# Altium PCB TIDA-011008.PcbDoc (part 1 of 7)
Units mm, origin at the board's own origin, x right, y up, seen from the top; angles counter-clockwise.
Board outline 252 x 205 mm, 4 copper layers (Top Layer, Inner Layer 1, Inner Layer 2, Bottom Layer), stack 1.926 mm thick; 517 components, 293 nets, 1426 pads, 1855 vias.
Unrouted connection lines stored in the file: 4.
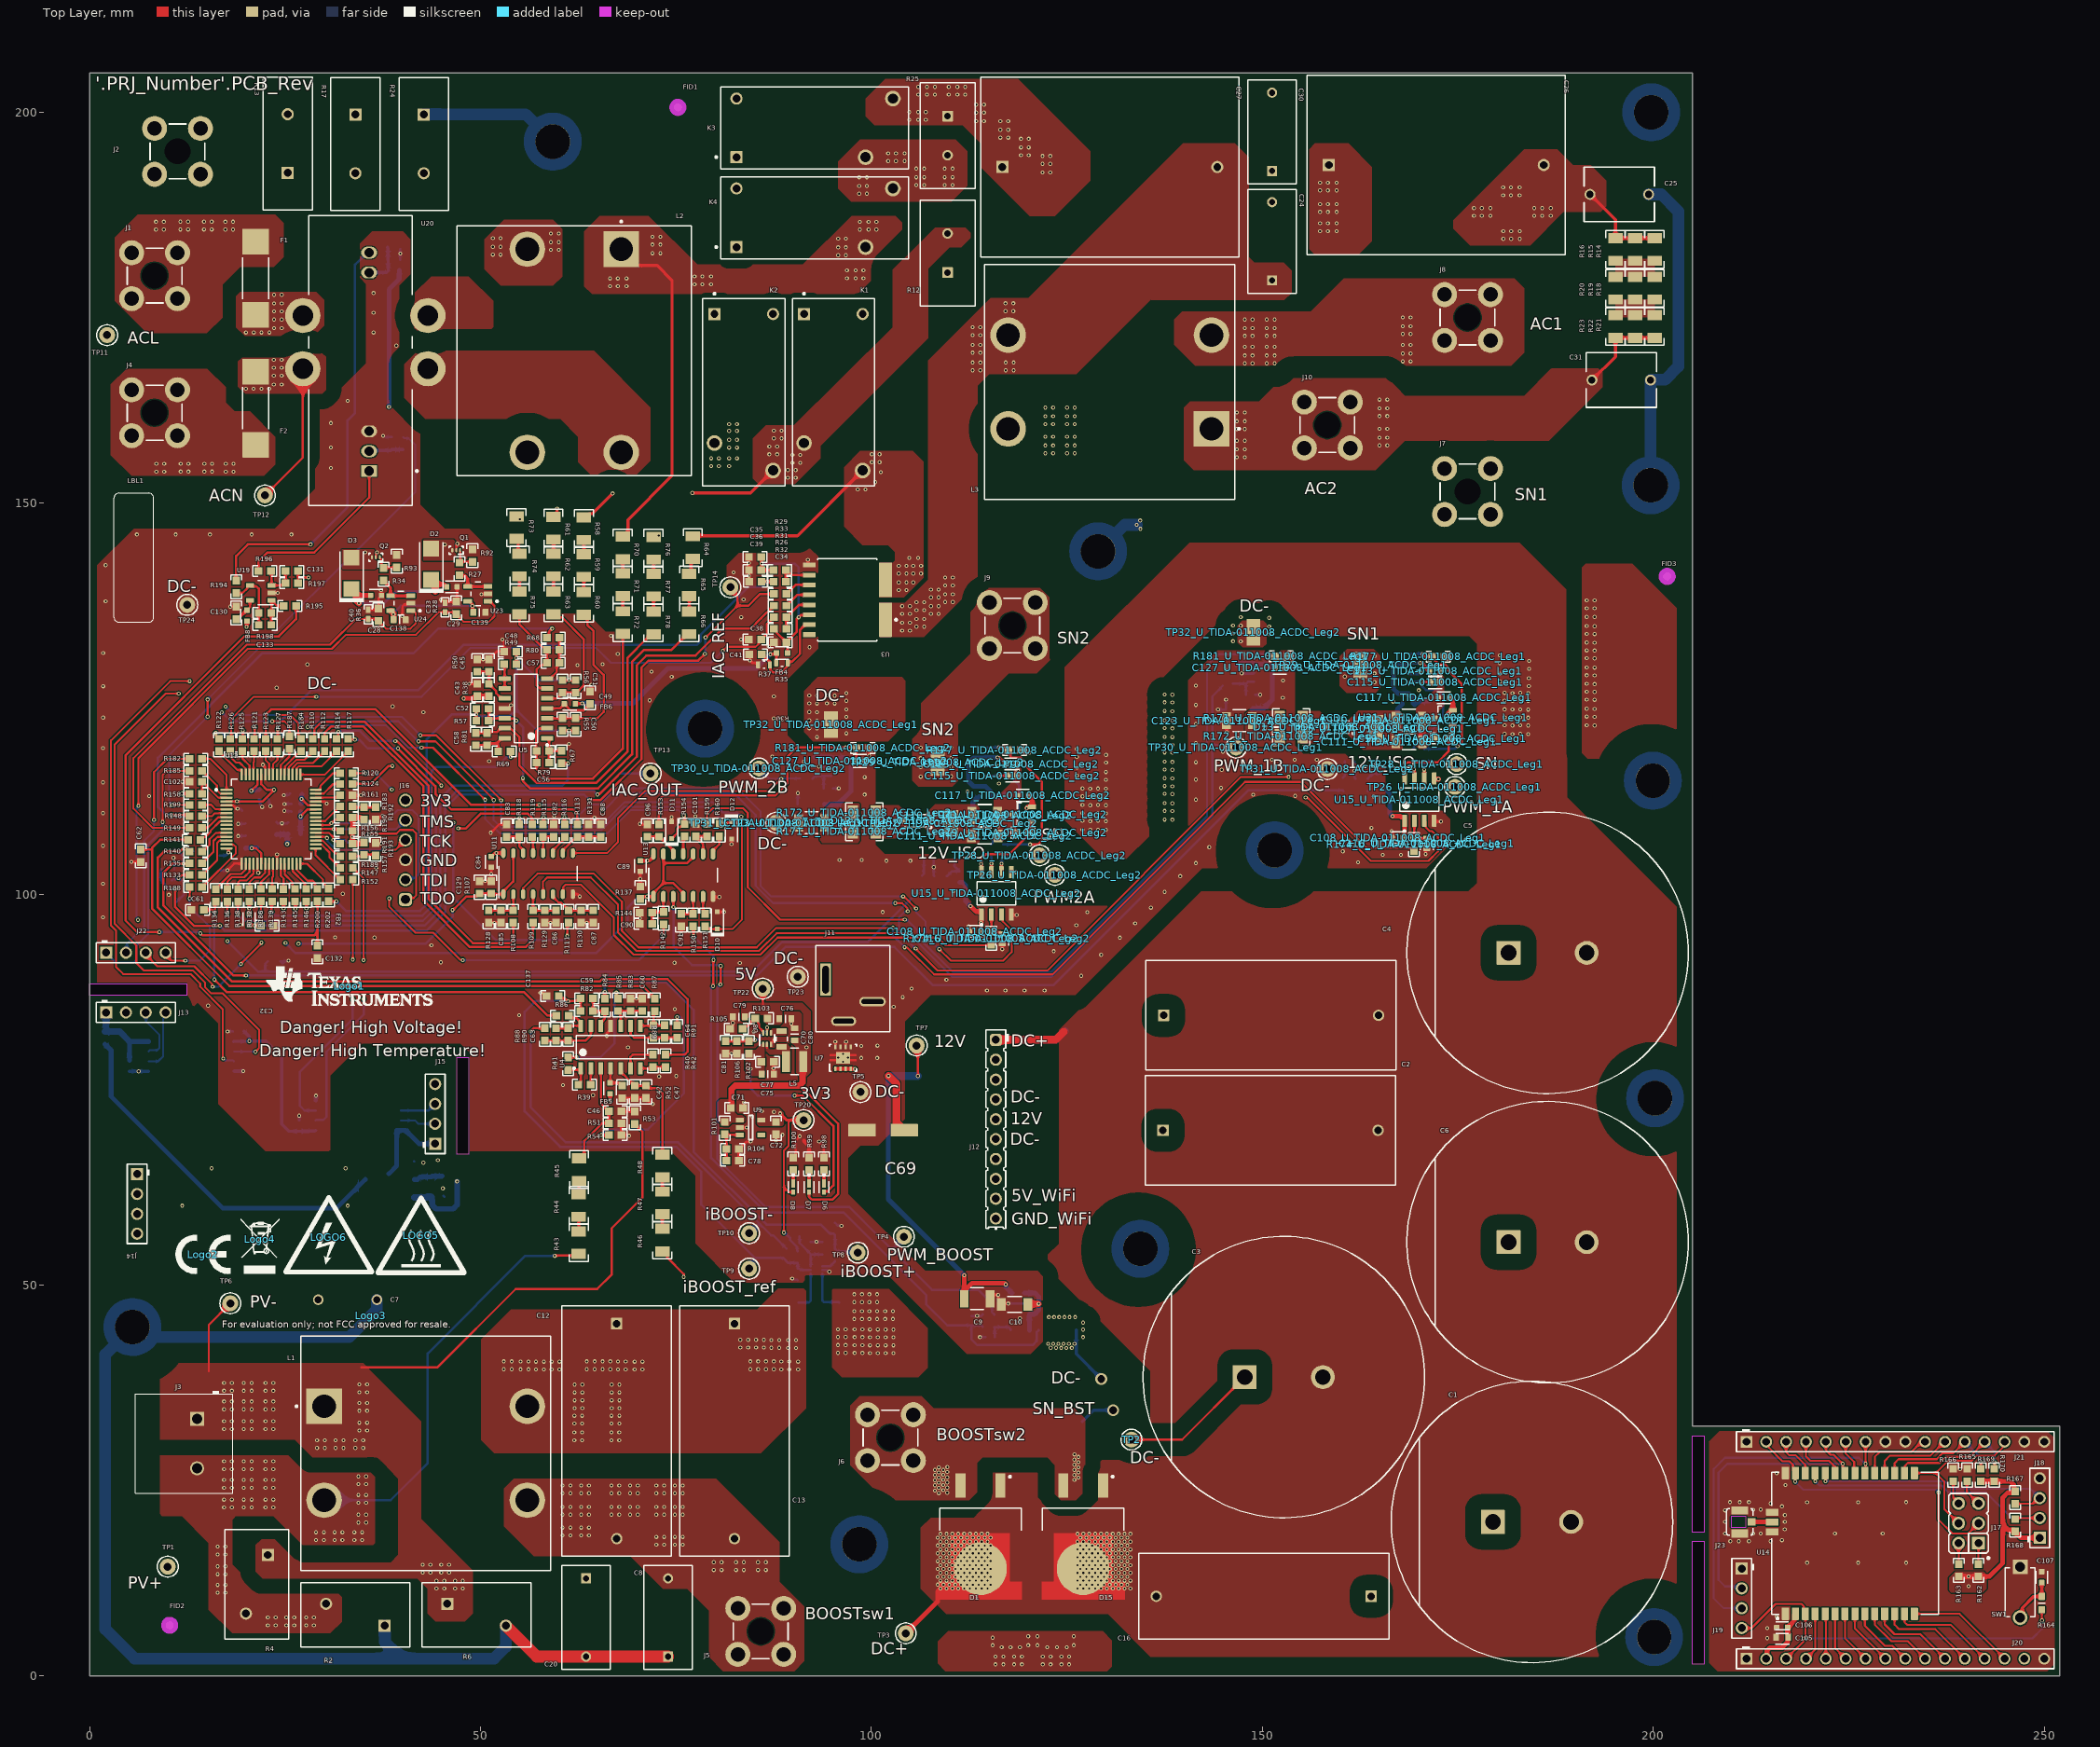
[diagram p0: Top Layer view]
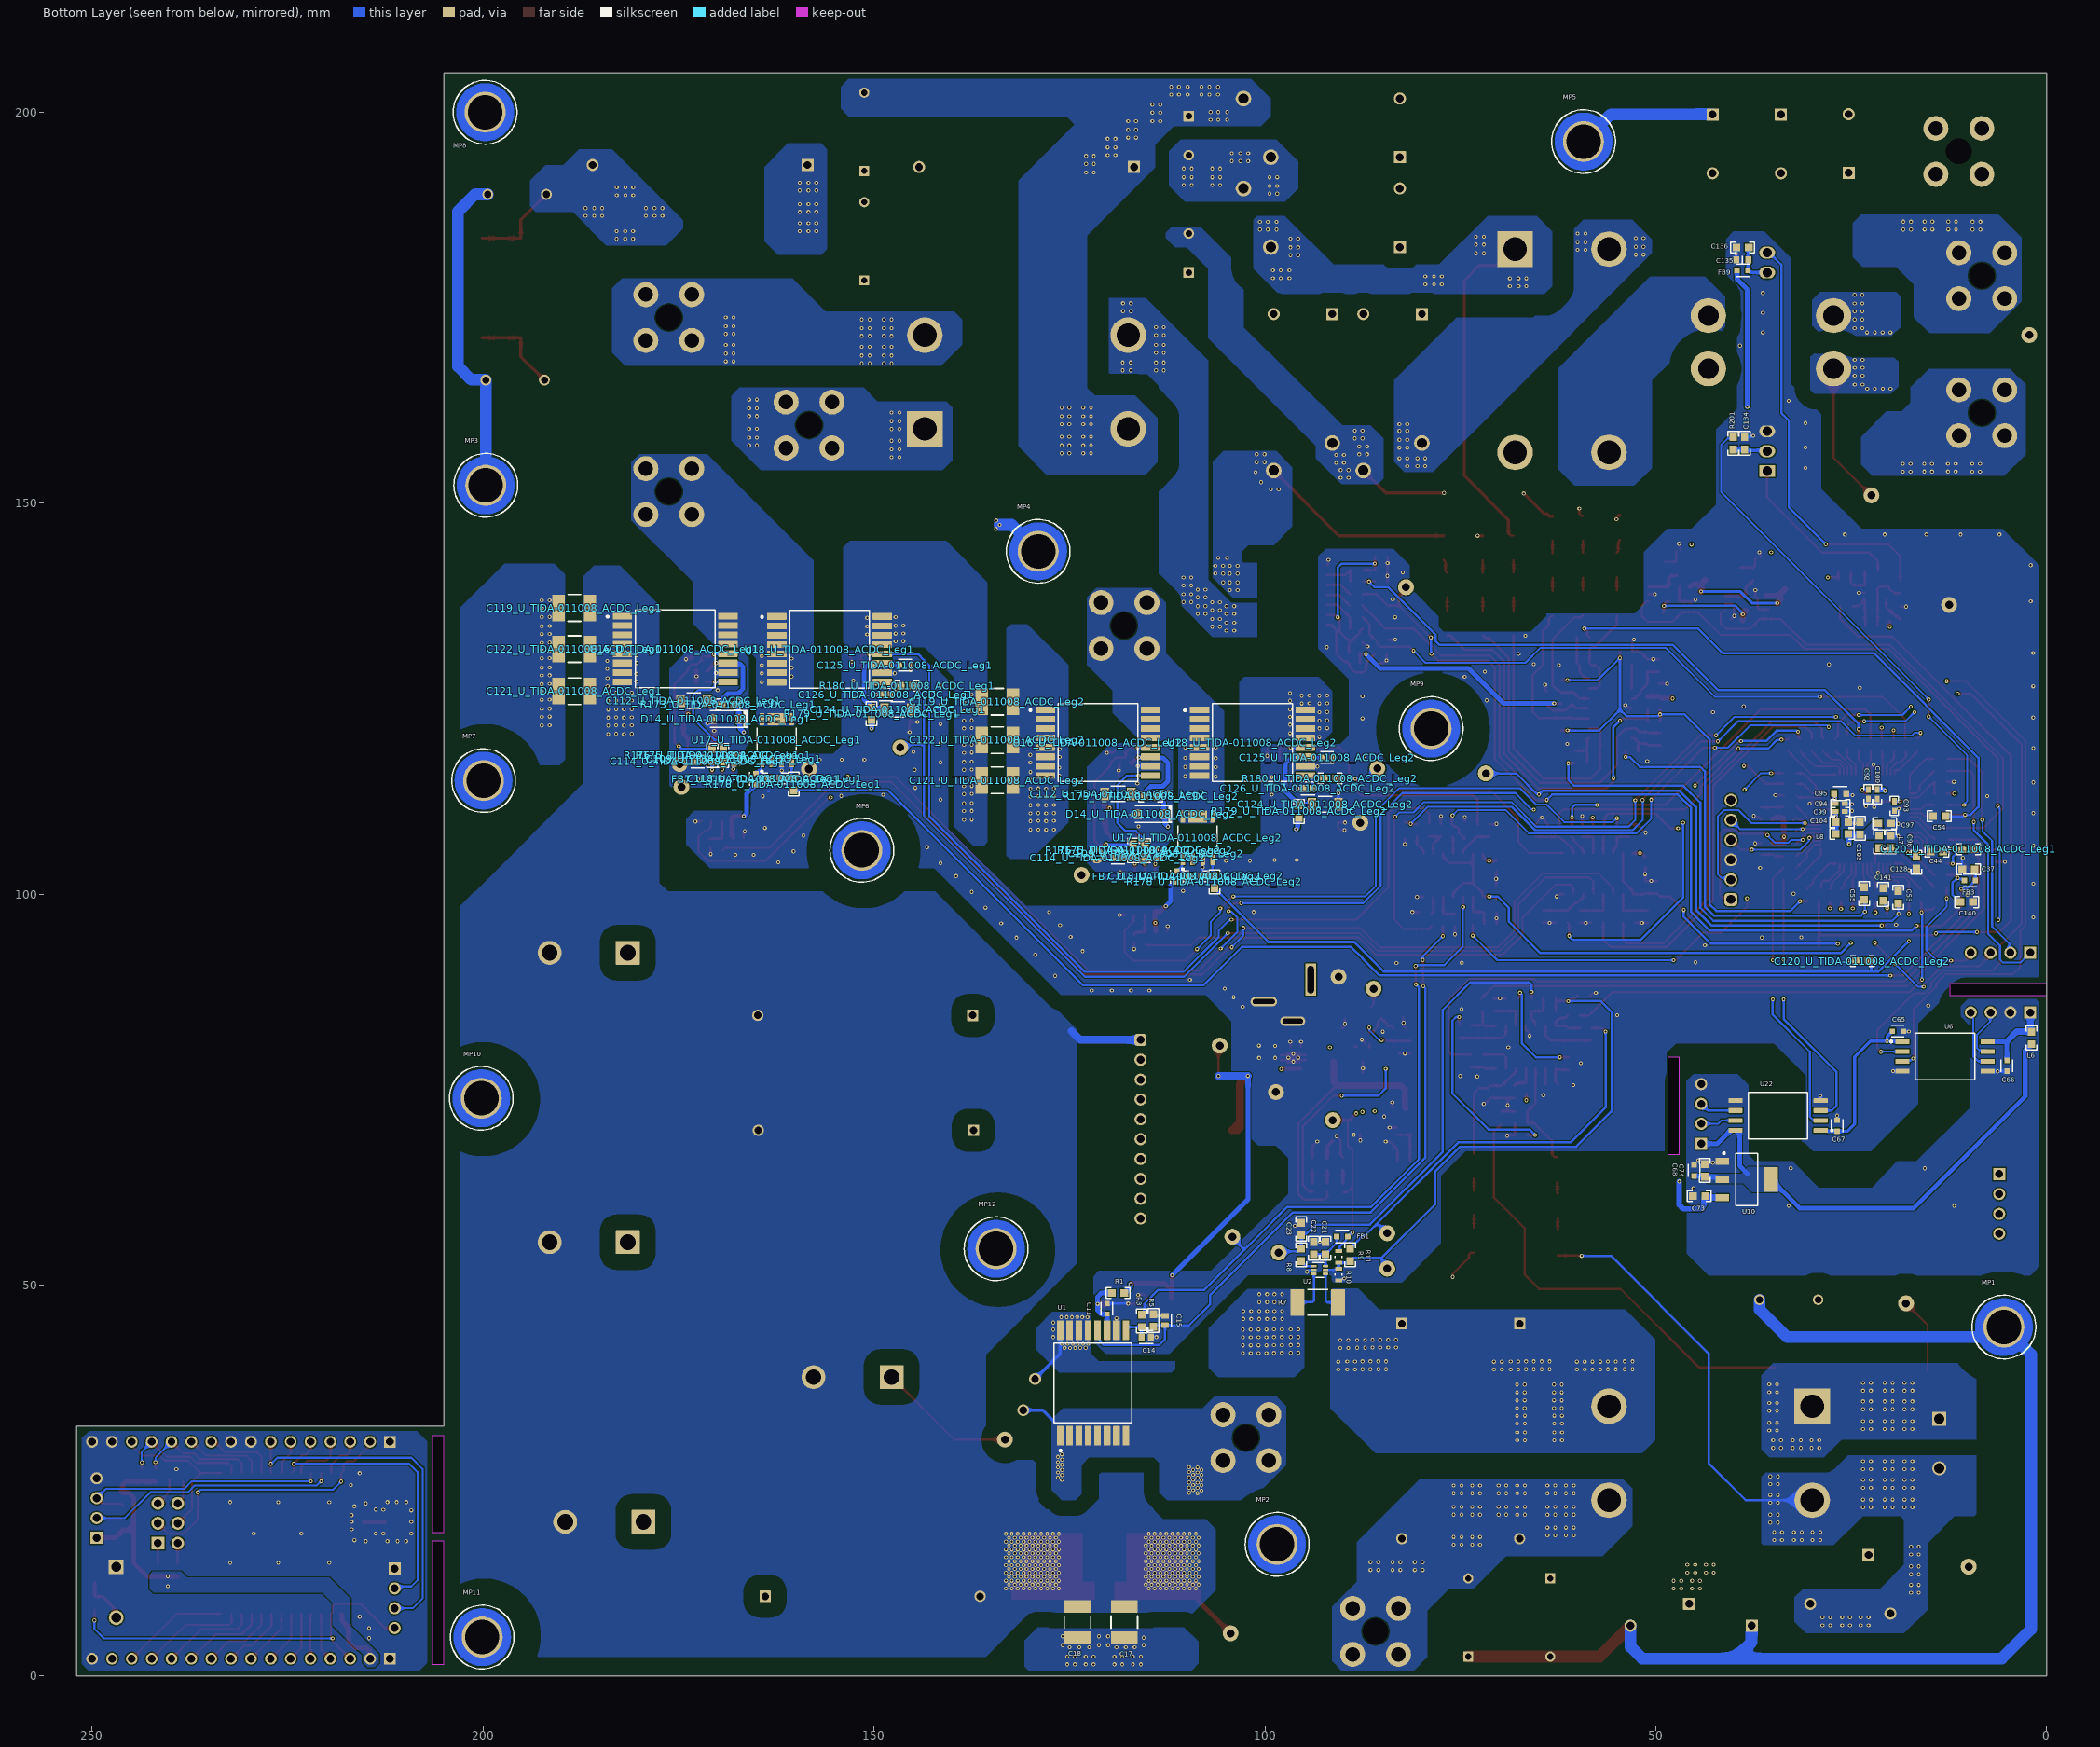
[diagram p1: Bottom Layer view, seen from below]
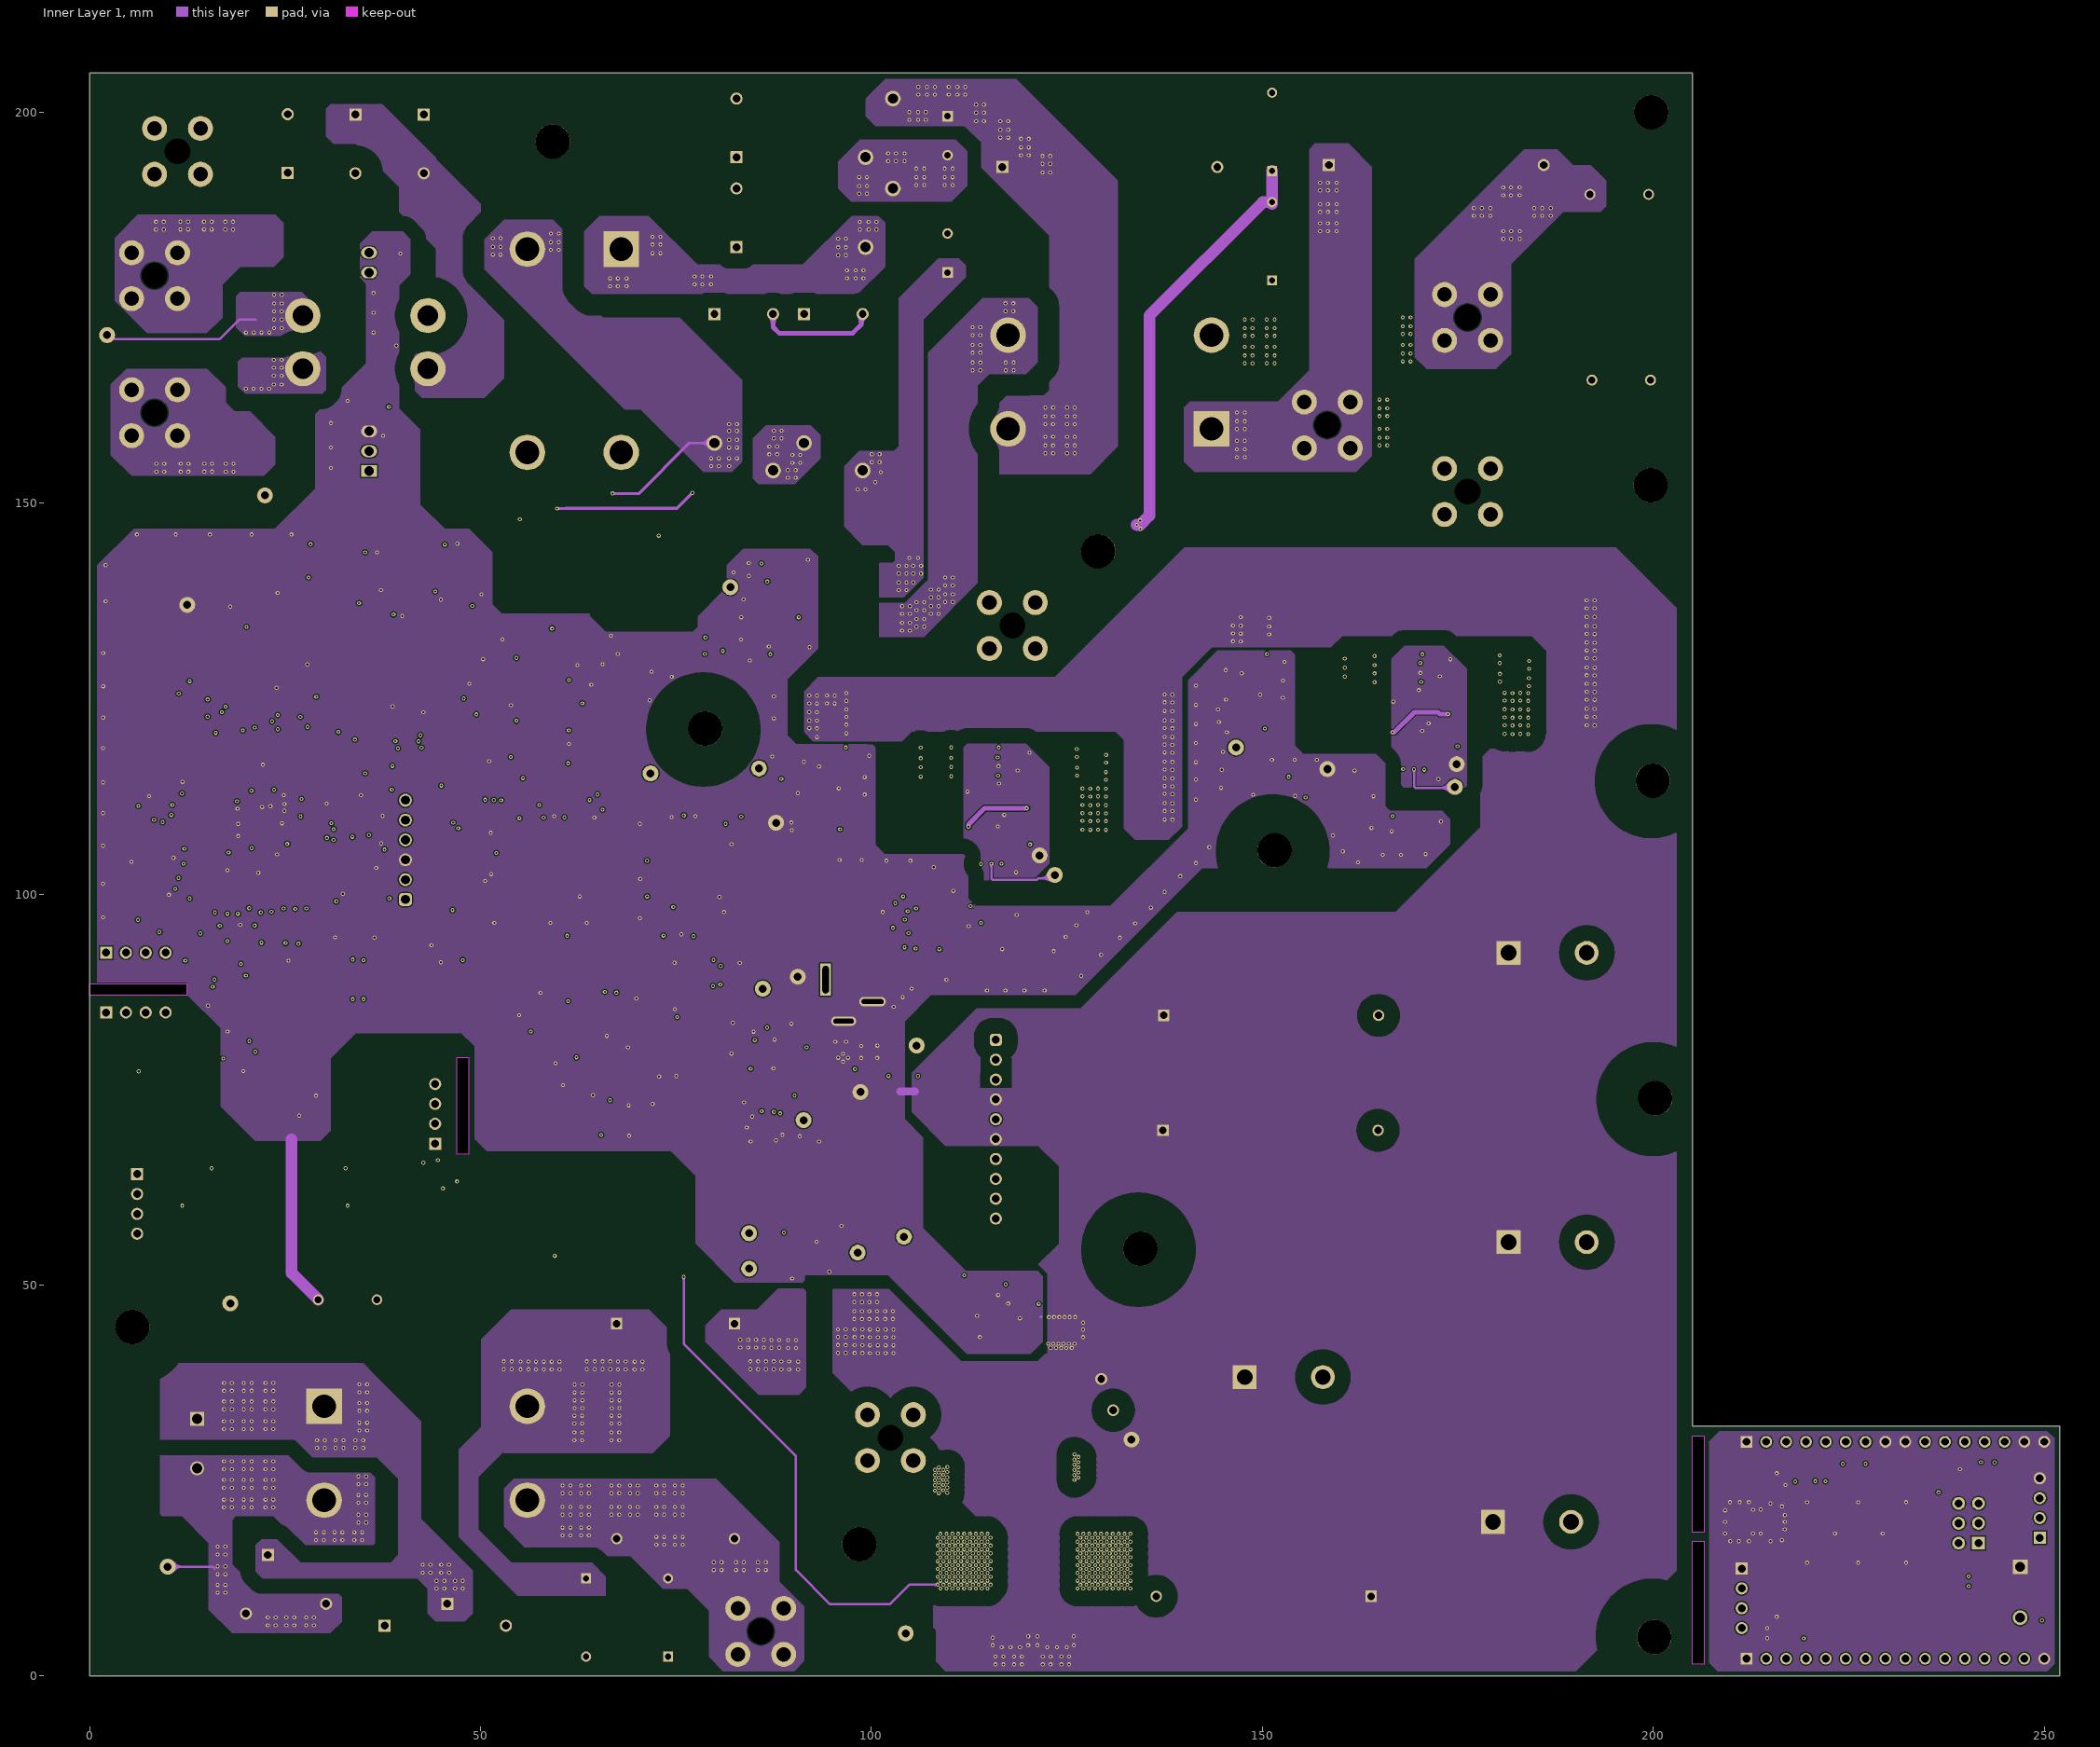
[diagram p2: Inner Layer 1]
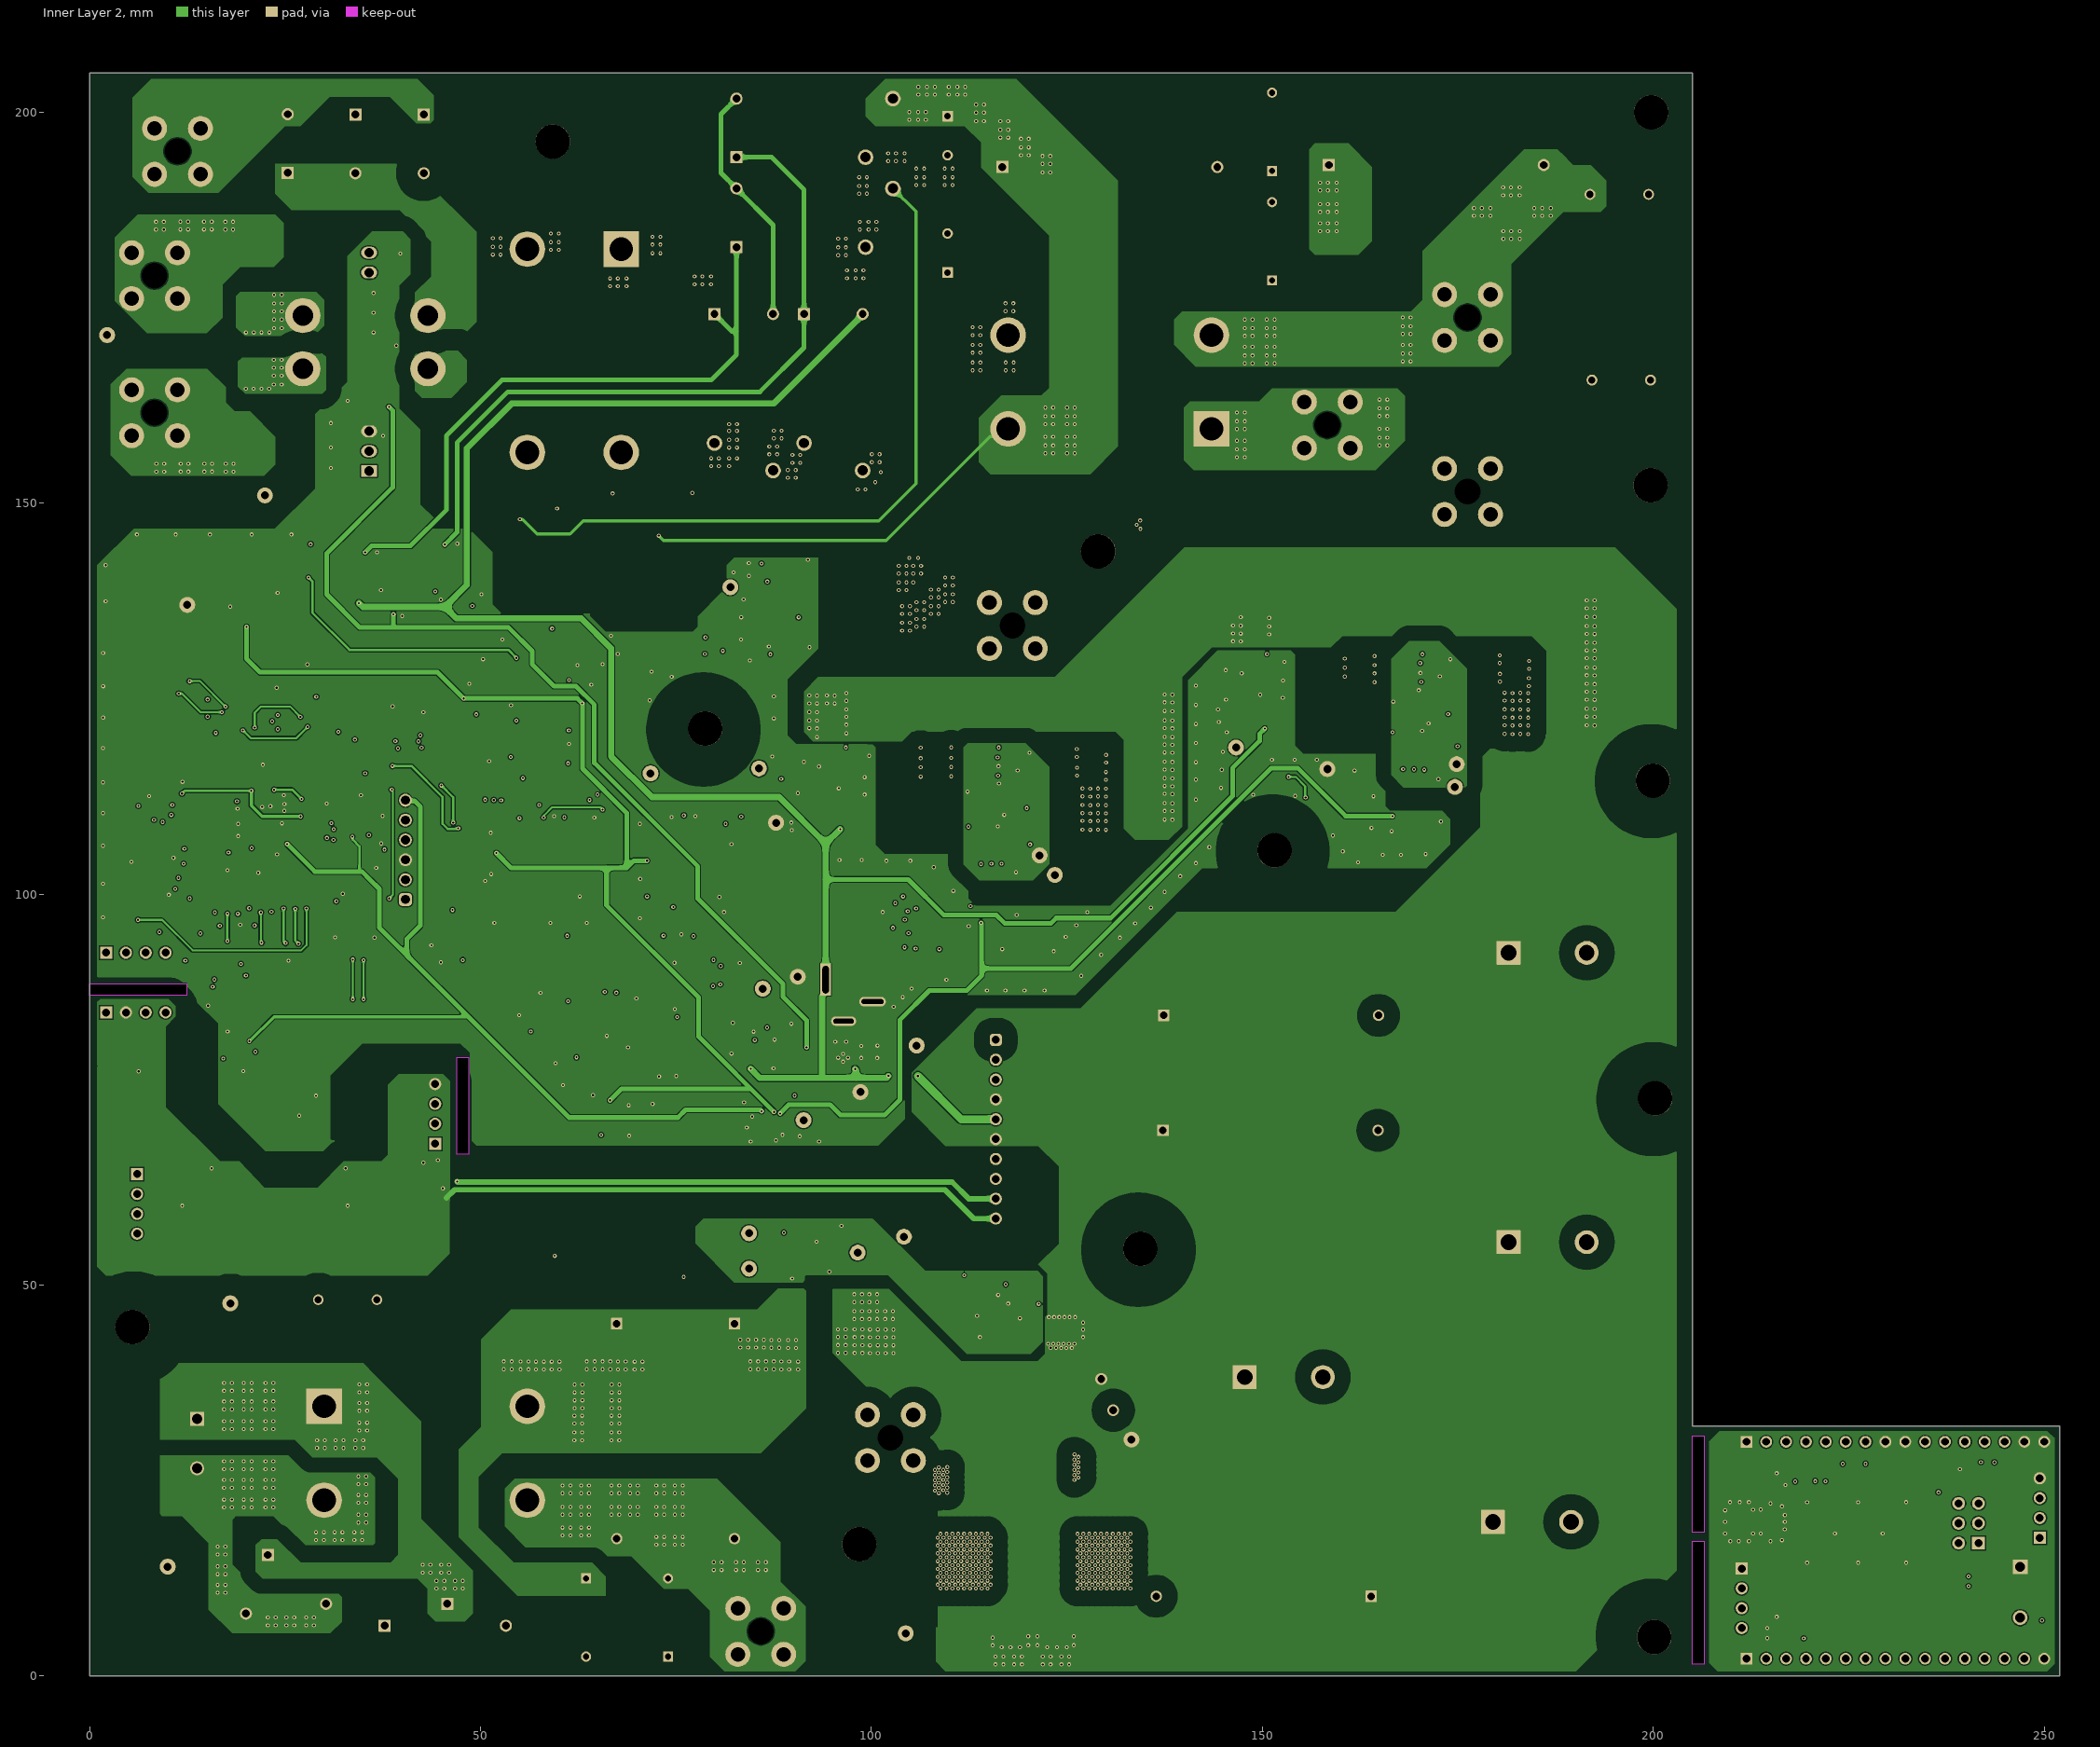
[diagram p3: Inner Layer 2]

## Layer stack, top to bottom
Top Solder: solder mask 0.0102, Solder Resist, Dk 3.5
Top Layer: signal copper 0.07
Dielectric 1: prepreg 0.0711, PP-006, Dk 4.1
Inner Layer 1: signal copper 0.07
Dielectric1: core 1.5037, FR-4 High Tg, Dk 4.8
Inner Layer 2: signal copper 0.07
Dielectric 2: prepreg 0.0711, PP-006, Dk 4.1
Bottom Layer: signal copper 0.07
Bottom Solder: solder mask 0.0102, Solder Resist, Dk 3.5

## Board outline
0,0 0,205 205,205 205,32 252,32 252,0
cut-out: 48.503,66.751 47.003,66.751 47.003,79.129 48.503,79.129
cut-out: 0.015,87.059 0.015,88.559 12.393,88.559 12.393,87.059
cut-out: 205,17.25 206.5,17.25 206.5,1.5 205,1.5
cut-out: 205,30.75 206.5,30.75 206.5,18.372 205,18.372

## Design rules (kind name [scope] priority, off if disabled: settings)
AcuteAngle [All] p1: minimum=4.50000000000000E+0001 checktracksonly=FALSE
AssemblyTestPointUsage [All] p1: valid=2
BoardOutlineClearance BoardOutlineClearance_MountingHoles [OnCopper and InComponentClass('Mounting Holes')] p1: gap=1 ignorepadtopadclearanceinfootprint=FALSE
BoardOutlineClearance BoardOutlineClearance_Poly [OnCopper and IsPoly] p2: gap=0.635 ignorepadtopadclearanceinfootprint=FALSE
BoardOutlineClearance [OnCopper and Not InComponentClass('Logo') and not InComponentClass('FiducialMark') and not InRegion(1000,500,4000,800) and not InPoly] p3: gap=1.016 ignorepadtopadclearanceinfootprint=FALSE
Clearance WiFi_HVN [InNetClass('GND_WiFi') vs InNetClass('HVN')] p1: gap=2.8 ignorepadtopadclearanceinfootprint=TRUE
Clearance SW_AC_Top [InNetClass('HV_SW1') vs (InNetClass('ACL')or InNetClass('ACN'))and (OnLayer('Top Layer') OR OnLayer('Bottom Layer'))] p2: gap=2 ignorepadtopadclearanceinfootprint=TRUE
Clearance SW_AC_Inner [InNetClass('HV_SW1') vs (InNetClass('ACL')or InNetClass('ACN'))and (OnLayer('Inner Layer 1') OR OnLayer('Inner Layer 2'))] p3: gap=1 ignorepadtopadclearanceinfootprint=TRUE
Clearance HVP_BOOST_SW_TOP [InNetClass('HVP') vs (InNetClass('HV_BOOST') or InNetClass('HV_BOOST_SW')) and (OnLayer('Top Layer') OR OnLayer('Bottom Layer'))] p4: gap=2 ignorepadtopadclearanceinfootprint=TRUE
Clearance HVP_BOOST_SW_INNER [InNetClass('HVP') vs (InNetClass('HV_BOOST') or InNetClass('HV_BOOST_SW')) and (OnLayer('Inner Layer 1') OR OnLayer('Inner Layer 2'))] p5: gap=1 ignorepadtopadclearanceinfootprint=TRUE
Clearance "Clearance Top HVN-HV" [InNetClass('HVN') vs (InNetClass('HVP') or InNetClass('HV_BOOST') or  InNetClass('HV_BOOST_SW') or InNetClass('HV_SW1') or InNetClass('ACN') or InNetClass('ACL'))] p6: gap=2 ignorepadtopadclearanceinfootprint=TRUE
Clearance "Clearance Inner HVN-HV" [InNetClass('HVN') vs (InNetClass('HVP') or InNetClass('HV_BOOST') or  InNetClass('HV_BOOST_SW') or InNetClass('HV_SW1') or InNetClass('ACN') or InNetClass('ACL')) and (OnLayer('Inner Layer 1') OR OnLayer('Inner Layer 2'))] p7: gap=1 ignorepadtopadclearanceinfootprint=TRUE
Clearance BUCK [InNetClass('HVP')   OR InNetClass('HVN') vs InNetClass('Buck')] p8: gap=1.8 ignorepadtopadclearanceinfootprint=FALSE
Clearance SW1 [(InNetClass('HVN')) OR (InNetClass('HVP')) vs InNetClass('HV_SW1')] p9: gap=0.6 ignorepadtopadclearanceinfootprint=FALSE
Clearance SW_BOOST [(InNetClass('HVP') or InNetClass('HV_BOOST') or  InNetClass('HV_BOOST_SW')) vs InNetClass('HV_SW1') or (InNetClass('ACN')) or (InNetClass('ACL'))] p10: gap=2.8 ignorepadtopadclearanceinfootprint=FALSE
Clearance ACL_ACN [InNetClass('ACL') vs InNetClass('ACN')] p11: gap=2.8 ignorepadtopadclearanceinfootprint=FALSE
Clearance PE [InNetClass('PE')] p12 off: gap=2.5 ignorepadtopadclearanceinfootprint=FALSE
Clearance Minimum_Distance [All] p13: gap=0.15 ignorepadtopadclearanceinfootprint=FALSE
Clearance Clearance_Keepouts [((IsTrack Or IsArc) And Not InPoly) And IsFree and IsKeepOut vs ((IsTrack Or IsArc) And Not InPoly) And IsFree and IsKeepOut] p14: gap=0 ignorepadtopadclearanceinfootprint=FALSE
Clearance Clearance_Poly [InPolygon] p15: gap=0.254 ignorepadtopadclearanceinfootprint=TRUE
Clearance Clearance_FiducialMark [IsKeepOut and InComponentClass('FiducialMark') vs IsPad and InComponentClass('FiducialMark')] p16: gap=0 ignorepadtopadclearanceinfootprint=TRUE
ComponentClearance ComponentClearance_MountingHoles_FiducialMarks [InComponentClass('Mounting Holes') vs InComponentClass('FiducialMark')] p1: gap=1.27 collisioncheckmode=3 verticalgap=0.254 showdistances=FALSE
ComponentClearance ComponentClearance_Shunt [InComponentClass('Header') vs InComponentClass('Shunt')] p2: gap=0 collisioncheckmode=3 verticalgap=0 showdistances=FALSE
ComponentClearance ComponentClearance_Logo [InComponentClass('Logo')] p3: gap=0 collisioncheckmode=3 verticalgap=0 showdistances=FALSE
ComponentClearance ComponentClearance_ScrewToNut [(HasFootprint('NY PMS 440 0025 PH')) vs (HasFootprint('Keystone_1902C'))] p4: gap=0.127 collisioncheckmode=3 verticalgap=0.254 showdistances=FALSE
ComponentClearance ComponentClearance_MountingHoles [InComponentClass('Mounting Holes')] p5: gap=2.54 collisioncheckmode=3 verticalgap=2540 showdistances=FALSE
ComponentClearance ComponentClearance_SmallPassives [HasFootprint('0201*') or HasFootprint('0402*') or HasFootprint('0508') or HasFootprint('0603*') or HasFootprint('0612') or HasFootprint('0805*') or HasFootprint('0815*') or HasFootprint('0830*') or HasFootprint('1206*') or HasFootprint('1210*') or HasFootprint('1808*') or HasFootprint('1812*') or HasFootprint('1825*') or HasFootprint('2010*') or HasFootprint('2220*') or HasFootprint('2225*') or HasFootprint('2512*') or HasFootprint('2728*') or HasFootprint('3518*') vs HasFootprint('0201*') or HasFootprint('0402*') or HasFootprint('0508') or HasFootprint('0603*') or HasFootprint('0612') or HasFootprint('0805*') or HasFootprint('0815*') or HasFootprint('0830*') or HasFootprint('1206*') or HasFootprint('1210*') or HasFootprint('1808*') or HasFootprint('1812*') or HasFootprint('1825*') or HasFootprint('2010*') or HasFootprint('2220*') or HasFootprint('2225*') or HasFootprint('2512*') or HasFootprint('2728*') or HasFootprint('3518*')] p6: gap=0.38 collisioncheckmode=3 verticalgap=0.254 showdistances=FALSE
ComponentClearance ComponentClearance_THtoSMT [IsThruComponent vs IsSMTComponent] p7: gap=0.01 collisioncheckmode=3 verticalgap=0.01 showdistances=FALSE
ComponentClearance ComponentClearance_THtoTH [IsThruComponent vs IsThruComponent] p8: gap=0.1 collisioncheckmode=3 verticalgap=0.1 showdistances=FALSE
ComponentClearance [All] p9: gap=0.01 collisioncheckmode=3 verticalgap=0.01 showdistances=FALSE
DiffPairsRouting [All] p1: maxlimit=2.54 minlimit=0.254 mostfreqgap=0.254 toplayer_minwidth=0.381 toplayer_maxwidth=0.381 toplayer_prefwidth=0.381 midlayer1_minwidth=0.381 midlayer1_maxwidth=0.381 midlayer1_prefwidth=0.381 midlayer2_minwidth=0.381 midlayer2_maxwidth=0.381 midlayer2_prefwidth=0.381 bottomlayer_minwidth=0.381 bottomlayer_maxwidth=0.381 bottomlayer_prefwidth=0.381 maxuncoupledlength=25.4
FabricationTestPointUsage TestPointUsage [All] p1: valid=2 allowmultiple=FALSE
FabricationTestpoint Testpoint [All] p1: side=3 testpointundercomponent=TRUE minsize=1.016 maxsize=2.54 preferedsize=1.524 minholesize=0 maxholesize=1.016 preferedholesize=0.813 testpointgrid=0.025 allowsidetop=TRUE allowsidebottom=TRUE usegrid=TRUE gridtolerance=0
FanoutControl Fanout_LCC [IsLCC] p1: bgadir=Out bgaviamode=Centered fanoutstyle=Auto fanoutdirection=Alternating viagrid=0.025 // Fanout_LCC (Default Rule)
FanoutControl Fanout_BGA [IsBGA] p2: bgadir=Out bgaviamode=Centered fanoutstyle=Auto fanoutdirection=Alternating viagrid=0.025 // Fanout_BGA (Default Rule)
FanoutControl Fanout_Default [All] p4: bgadir=Out bgaviamode=Centered fanoutstyle=Auto fanoutdirection=Alternating viagrid=0.025 // Fanout_Default (Default Rule)
FanoutControl Fanout_Small [(CompPinCount < 5)] p5: bgadir=Out bgaviamode=Centered fanoutstyle=Auto fanoutdirection=OutThenIn viagrid=0.025 // Fanout_Small (Default Rule)
HoleSize [All] p1: absolutevalues=TRUE maxlimit=6.375 minlimit=0.2 maxpercent=80.000 minpercent=20.000
MinimumAnnularRing MinimumAnnularRing_ThermalPadVias [IsVia and InAnyComponent] p1: minimumring=0.15
MinimumAnnularRing [All] p2: minimumring=0.125
MinimumSolderMaskSliver MinimumSolderMaskSliver_Logo [InComponentClass('Logo') vs InComponentClass('Logo')] p1: minsoldermaskwidth=0.018
MinimumSolderMaskSliver [All] p2: minsoldermaskwidth=0
PlaneConnect [All] p1: planeconnectstyle=Relief reliefexpansion=0.254 reliefentries=4 reliefconductorwidth=0.254 reliefairgap=0.254
PolygonConnect PolygonConnect_1 [All] p1: connectstyle=Direct reliefconductorwidth=1 reliefentries=4 polygonreliefangle="90 Angle" airgapwidth=0.254
PolygonConnect "GaN 2" [IsNamedPolygon('BOTTOM_LAYER_SN2_P047') vs HasFootprint('KLF0016A-MFG')] p2: connectstyle=Relief reliefconductorwidth=0.254 reliefentries=4 polygonreliefangle="90 Angle" airgapwidth=0.254
PolygonConnect "GaN 3" [IsNamedPolygon('BOTTOM_LAYER_SW_MID_P059')] p3: thpad.connectstyle=Direct thpad.reliefconductorwidth=0.254 thpad.reliefentries=4 thpad.polygonreliefangle="90 Angle" thpad.airgapwidth=0.254 smdpad.connectstyle=Relief smdpad.reliefconductorwidth=0.254 smdpad.reliefentries=4 smdpad.polygonreliefangle="90 Angle" smdpad.airgapwidth=0.254 via.connectstyle=Direct via.reliefconductorwidth=0.254 via.reliefentries=4 via.polygonreliefangle="90 Angle" via.airgapwidth=0.254
PolygonConnect "GaN 4" [IsNamedPolygon('BOTTOM_LAYER_DC_BUS+_P066')] p4: thpad.connectstyle=Direct thpad.reliefconductorwidth=0.254 thpad.reliefentries=4 thpad.polygonreliefangle="90 Angle" thpad.airgapwidth=0.254 smdpad.connectstyle=Relief smdpad.reliefconductorwidth=0.254 smdpad.reliefentries=4 smdpad.polygonreliefangle="90 Angle" smdpad.airgapwidth=0.254 via.connectstyle=Direct via.reliefconductorwidth=0.254 via.reliefentries=4 via.polygonreliefangle="90 Angle" via.airgapwidth=0.254
PolygonConnect "GaN 5" [IsNamedPolygon('Bottom Layer-SW_1')] p5: thpad.connectstyle=Direct thpad.reliefconductorwidth=0.254 thpad.reliefentries=4 thpad.polygonreliefangle="90 Angle" thpad.airgapwidth=0.254 smdpad.connectstyle=Relief smdpad.reliefconductorwidth=0.254 smdpad.reliefentries=4 smdpad.polygonreliefangle="90 Angle" smdpad.airgapwidth=0.254 via.connectstyle=Direct via.reliefconductorwidth=0.254 via.reliefentries=4 via.polygonreliefangle="90 Angle" via.airgapwidth=0.254
PolygonConnect "GaN 6" [IsNamedPolygon('BOTTOM_LAYER_DC_BUS+_P007')] p6: thpad.connectstyle=Direct thpad.reliefconductorwidth=0.254 thpad.reliefentries=4 thpad.polygonreliefangle="90 Angle" thpad.airgapwidth=0.254 smdpad.connectstyle=Relief smdpad.reliefconductorwidth=0.254 smdpad.reliefentries=4 smdpad.polygonreliefangle="90 Angle" smdpad.airgapwidth=0.254 via.connectstyle=Direct via.reliefconductorwidth=0.254 via.reliefentries=4 via.polygonreliefangle="90 Angle" via.airgapwidth=0.254
PolygonConnect "GaN 7" [IsNamedPolygon('BOTTOM_LAYER_DC_BUS-_P082')] p7: thpad.connectstyle=Direct thpad.reliefconductorwidth=0.254 thpad.reliefentries=4 thpad.polygonreliefangle="90 Angle" thpad.airgapwidth=0.254 smdpad.connectstyle=Relief smdpad.reliefconductorwidth=0.254 smdpad.reliefentries=4 smdpad.polygonreliefangle="90 Angle" smdpad.airgapwidth=0.254 via.connectstyle=Direct via.reliefconductorwidth=0.254 via.reliefentries=4 via.polygonreliefangle="90 Angle" via.airgapwidth=0.254
PolygonConnect [All] p8: connectstyle=Direct reliefconductorwidth=0.254 reliefentries=4 polygonreliefangle="90 Angle" airgapwidth=0.254
RoutingVias ThermalPadVias [IsVia and InAnyComponent] p1: holewidth=0.254 width=0.508 viastyle="Through Hole" minholewidth=0.2 minwidth=0.5 maxholewidth=1.016 maxwidth=1.651
RoutingVias [All] p2: holewidth=0.406 width=0.864 viastyle="Through Hole" minholewidth=0.2 minwidth=0.5 maxholewidth=1.016 maxwidth=1.651
SilkToBoardRegionClearance [Not ((IsComment or IsDesignator) And (Hide <> 'False')) and not InRegion(1000,500,4000,800)] p1:
SilkToSilkClearance SilkToSilkClearance_Pb-FreeLogo [(HasFootprint('Pb-Free_Overlay_Medium') OR HasFootprint('Pb-Free_Overlay_Small')) vs (HasFootprint('Pb-Free_Overlay_Medium') OR HasFootprint('Pb-Free_Overlay_Small'))] p1: silktosilkclearance=0
SilkToSilkClearance [All] p2: silktosilkclearance=0
SilkToSolderMaskClearance SilkToComponentPadClearance [(IsPad or IsFill or IsRegion) and InAnycomponent] p1: minsilkscreentomaskgap=0 clearancetoexposedcopper=TRUE
SilkToSolderMaskClearance "Silk to Solder Mask Opening" [All] p2: minsilkscreentomaskgap=0.01 clearancetoexposedcopper=FALSE
SolderMaskExpansion [All] p1: expansion=0.05 istentingtop=FALSE
UnRoutedNet [All] p1: checkbadconnections=TRUE
Width [All] p1: maxlimit=2.54 minlimit=0.25 preferedwidth=0.5 checkconnectedcopper=TRUE
14 further rules are at their usual default settings.

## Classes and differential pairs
net class GND_WiFi: ANT2 GND_WiFi GPRS_RX GPRS_TX LOGGER NetC66_2 NetC107_2 NetJ17_1 NetJ17_2 NetJ17_5 NetJ17_6 P12_GPIO32 P13_GPIO31 P14_GPIO30 P16_GPIO29 P17_GPIO28 P18_GPIO27 P19_GPIO26 P29_GPIO17 P30_GPIO16 P31_GPIO15 P32_GPIO14 P33_GPIO13 P34_GPIO12 P35_GPIO11 P36_GPIO10 P43_GPIO4 P44_GPIO3 P52_GPIO37 P53_GPIO36 RESET SWCLK SWDIO UART1_RX UART1_TX VCC_3V3_Wifi VCC_5V_WiFi
component class U_TIDA-011008_Hardware: !PCB FID1 FID2 FID3 LBL1 Logo1 Logo2 Logo3 Logo4 LOGO5 LOGO6 MP1 MP2 MP3 MP4 MP5 MP6 MP7 MP8 MP9 MP10 MP11 MP12
component class Logo: Logo1
component class Label: LBL1
component class FiducialMark: FID1 FID2 FID3
net class HV_BOOST_SW: NetD1_3
channel class TIDA-011008_ACDC_Leg: U_TIDA-011008_ACDC_Leg1 U_TIDA-011008_ACDC_Leg2
net class PE: PE PE1 PE2 PE3 PE4 PE5
net class HVP: DC_Bus+
net class HVN: CS_Boost CS_Boost+ CS_Boost- CS_Boost_ref DAC_A DC_Bus- Enable_DCAC Enable_DCDC FLT_1A FLT_1A_mcu FLT_1B FLT_1B_mcu FLT_2A FLT_2A_mcu FLT_2B FLT_2B_mcu FLT_Boost FLT_Boost_mcu GPIO24 GPIO28 GPIO29 GPIO32 GPIO227 IAC_F\A\U\L\T\ IAC_O\C\ IAC_OUT IAC_REF MCU_TCK MCU_TDI MCU_TDO MCU_TMS NetC10_1 NetC12_1 NetC21_1 NetC32_2 NetC34_1 NetC37_2 NetC41_1 NetC45_2 NetC49_1 NetC50_1 NetC51_1 NetC52_1 NetC56_1 NetC56_2 NetC57_1 NetC57_2 NetC58_1 NetC58_2 NetC59_2 NetC60_2 NetC63_1 NetC63_2 NetC64_1 NetC64_2 NetC70_1 NetC70_2 NetC78_2 NetC81_2 NetC82_1 NetC83_1 NetC85_1 NetC86_1 NetC87_1 NetC88_1 NetC90_1 NetC91_1 NetC96_1 NetC101_1 NetC102_1 NetC116_U_TIDA-011008_ACDC_Leg1_1 NetC116_U_TIDA-011008_ACDC_Leg2_1 NetC118_U_TIDA-011008_ACDC_Leg1_1 NetC118_U_TIDA-011008_ACDC_Leg2_1 NetC124_U_TIDA-011008_ACDC_Leg1_1 NetC124_U_TIDA-011008_ACDC_Leg2_1 NetC128_2 NetC130_1 NetC131_1 NetC133_1 NetC133_2 NetC134_1 NetD6_1 NetD7_1 NetD8_1 NetD13_U_TIDA-011008_ACDC_Leg1_2 NetD13_U_TIDA-011008_ACDC_Leg2_2 NetQ1_1 NetQ2_1 NetR8_1 NetR26_1 NetR27_1 NetR29_1 NetR30_1 NetR31_2 NetR34_1 NetR49_1 NetR103_1 NetR110_1 NetR112_1 NetR114_1 NetR116_1 NetR117_1 NetR119_1 NetR120_1 NetR121_1 NetR122_1 NetR123_1 NetR124_1 NetR125_1 NetR126_1 NetR127_1 NetR132_1 NetR133_1 NetR134_1 NetR135_1 NetR136_1 NetR138_1 NetR139_1 NetR140_1 NetR141_1 NetR143_1 NetR145_1 NetR146_1 NetR147_1 NetR148_1 NetR149_1 NetR151_1 NetR152_1 NetR154_1 NetR160_1 NetR161_1 NetR178_U_TIDA-011008_ACDC_Leg1_2 NetR178_U_TIDA-011008_ACDC_Leg2_2 NetR182_1 NetR183_1 NetR184_1 NetR185_1 NetR186_1 NetR187_1 NetR188_1 NetR189_1 NetR199_1 NetR200_1 NetR202_1 PV_Input- PV_Input_buffer+ PV_Input_buffer- PWM_1A PWM_1A_mcu PWM_1B PWM_1B_mcu PWM_2A PWM_2A_mcu PWM_2B PWM_2B_mcu PWM_Boost PWM_Boost_mcu PWMiN_B_U_TIDA-011008_ACDC_Leg1 PWMiN_B_U_TIDA-011008_ACDC_Leg2 PWMiN_Boost Relay_Precharge Relay_Precharge_mcu Relay_Safe Relay_Safe_mcu SCIA_RX SCIA_TX SCIB_RX SCIB_TX TEMP_SW1 TEMP_SW2 V_ZCD VAC_input VAC_relay VAC_sw VCC_1V2 VCC_1V65 VCC_3V3 VCC_5V VCC_12V VCC_ZCD VCCA_3V3 VCCIO_3V3 VDC_sense Vout_ZCD VPV_sense Vref_ZCD ZCD_CHK
net class HV_SW1: FLT_A_LMG_U_TIDA-011008_ACDC_Leg1 FLT_A_LMG_U_TIDA-011008_ACDC_Leg2 LDO5V_SN_U_TIDA-011008_ACDC_Leg1 LDO5V_SN_U_TIDA-011008_ACDC_Leg2 NetC112_U_TIDA-011008_ACDC_Leg1_1 NetC112_U_TIDA-011008_ACDC_Leg2_1 NetC114_U_TIDA-011008_ACDC_Leg1_2 NetC114_U_TIDA-011008_ACDC_Leg2_2 NetR175_U_TIDA-011008_ACDC_Leg1_1 NetR175_U_TIDA-011008_ACDC_Leg2_1 PWMiN_A_U_TIDA-011008_ACDC_Leg1 PWMiN_A_U_TIDA-011008_ACDC_Leg2 SN1 SN2 SN_U_TIDA-011008_ACDC_Leg1 SN_U_TIDA-011008_ACDC_Leg2 VCC_12V_SN_U_TIDA-011008_ACDC_Leg1 VCC_12V_SN_U_TIDA-011008_ACDC_Leg2
net class HV_BOOST: NetC8_2 PV_Input+
net class ACN: AC_N NetC26_1 NetF2_1 NetL2_4 VAC_N VAC_N_Relay VAC_N_SW
net class ACL: AC_L NetC24_1 NetC25_2 NetF1_1 NetL2_3 VAC_L VAC_L_Relay VAC_L_SW
component class "U_TIDA-011008_WiFi Module": ANT1 C105 C106 C107 J17 J18 J19 J20 J21 J23 R162 R163 R164 R165 R166 R167 R168 R169 R170 SW1 U14
component class "U_TIDA-011008_Measurements & AD Buffer": C42 C43 C44 C45 C46 C47 C48 C49 C50 C51 C52 C53 C54 C55 C56 C57 C58 C59 C60 C61 C62 C63 C64 C130 C131 C132 C133 FB5 FB6 FB8 R38 R39 R40 R41 R42 R43 R44 R45 R46 R47 R48 R49 R50 R51 R52 R53 R54 R55 R56 R57 R58 R59 R60 R61 R62 R63 R64 R65 R66 R67 R68 R69 R70 R71 R72 R73 R74 R75 R76 R77 R78 R79 R80 R81 R82 R83 R84 R85 R86 R87 R88 R89 R90 R91 R194 R195 R196 R197 R198 U4 U5 U19
component class "U_TIDA-011008_Control Stage": C65 C66 C67 C68 C73 C74 C82 C83 C84 C85 C86 C87 C88 C89 C90 C91 C92 C93 C94 C95 C96 C97 C98 C99 C100 C101 C102 C103 C104 C128 C129 D10 D11 D12 J13 J14 J15 J16 J22 L6 L7 L8 R107 R109 R110 R112 R113 R114 R115 R116 R117 R118 R119 R120 R121 R122 R123 R124 R125 R126 R127 R128 R129 R130 R131 R132 R133 R134 R135 R136 R137 R138 R139 R140 R141 R142 R143 R144 R145 R146 R147 R148 R149 R150 R151 R152 R153 R154 R155 R156 R157 R158 R159 R160 R161 R182 R183 R184 R185 R186 R187 R188 R189 R190 R191 R192 R193 R199 R200 R202 TP24 U6 U10 U11 U12 U13 U22
component class U_TIDA-011008_Boost: C8 C9 C10 C11 C12 C13 C14 C15 C16 C17 C18 C20 C21 C22 C23 C137 D1 D15 FB1 J5 J6 L1 R1 R2 R3 R4 R5 R6 R7 R8 R9 R10 R11 TP1 TP2 TP3 TP4 TP5 TP6 TP8 TP9 TP10 U1 U2
component class "U_TIDA-011008_Aux Power": C69 C70 C71 C72 C75 C76 C77 C78 C79 C80 C81 D6 D7 D8 J11 J12 L5 R98 R99 R100 R101 R102 R103 R104 R105 R106 TP7 TP20 TP22 TP23 U7 U8 U9
component class U_TIDA-011008_ACDC_Leg2: C19_U_TIDA-011008_ACDC_Leg2 C108_U_TIDA-011008_ACDC_Leg2 C109_U_TIDA-011008_ACDC_Leg2 C110_U_TIDA-011008_ACDC_Leg2 C111_U_TIDA-011008_ACDC_Leg2 C112_U_TIDA-011008_ACDC_Leg2 C113_U_TIDA-011008_ACDC_Leg2 C114_U_TIDA-011008_ACDC_Leg2 C115_U_TIDA-011008_ACDC_Leg2 C116_U_TIDA-011008_ACDC_Leg2 C117_U_TIDA-011008_ACDC_Leg2 C118_U_TIDA-011008_ACDC_Leg2 C119_U_TIDA-011008_ACDC_Leg2 C120_U_TIDA-011008_ACDC_Leg2 C121_U_TIDA-011008_ACDC_Leg2 C122_U_TIDA-011008_ACDC_Leg2 C123_U_TIDA-011008_ACDC_Leg2 C124_U_TIDA-011008_ACDC_Leg2 C125_U_TIDA-011008_ACDC_Leg2 C126_U_TIDA-011008_ACDC_Leg2 C127_U_TIDA-011008_ACDC_Leg2 D13_U_TIDA-011008_ACDC_Leg2 D14_U_TIDA-011008_ACDC_Leg2 FB7_U_TIDA-011008_ACDC_Leg2 R171_U_TIDA-011008_ACDC_Leg2 R172_U_TIDA-011008_ACDC_Leg2 R173_U_TIDA-011008_ACDC_Leg2 R175_U_TIDA-011008_ACDC_Leg2 R176_U_TIDA-011008_ACDC_Leg2 R177_U_TIDA-011008_ACDC_Leg2 R178_U_TIDA-011008_ACDC_Leg2 R179_U_TIDA-011008_ACDC_Leg2 R180_U_TIDA-011008_ACDC_Leg2 R181_U_TIDA-011008_ACDC_Leg2 TP15_U_TIDA-011008_ACDC_Leg2 TP26_U_TIDA-011008_ACDC_Leg2 TP28_U_TIDA-011008_ACDC_Leg2 TP29_U_TIDA-011008_ACDC_Leg2 TP30_U_TIDA-011008_ACDC_Leg2 TP31_U_TIDA-011008_ACDC_Leg2 TP32_U_TIDA-011008_ACDC_Leg2 U15_U_TIDA-011008_ACDC_Leg2 U16_U_TIDA-011008_ACDC_Leg2 U17_U_TIDA-011008_ACDC_Leg2 U18_U_TIDA-011008_ACDC_Leg2 U21_U_TIDA-011008_ACDC_Leg2
component class U_TIDA-011008_ACDC_Leg1: C19_U_TIDA-011008_ACDC_Leg1 C108_U_TIDA-011008_ACDC_Leg1 C109_U_TIDA-011008_ACDC_Leg1 C110_U_TIDA-011008_ACDC_Leg1 C111_U_TIDA-011008_ACDC_Leg1 C112_U_TIDA-011008_ACDC_Leg1 C113_U_TIDA-011008_ACDC_Leg1 C114_U_TIDA-011008_ACDC_Leg1 C115_U_TIDA-011008_ACDC_Leg1 C116_U_TIDA-011008_ACDC_Leg1 C117_U_TIDA-011008_ACDC_Leg1 C118_U_TIDA-011008_ACDC_Leg1 C119_U_TIDA-011008_ACDC_Leg1 C120_U_TIDA-011008_ACDC_Leg1 C121_U_TIDA-011008_ACDC_Leg1 C122_U_TIDA-011008_ACDC_Leg1 C123_U_TIDA-011008_ACDC_Leg1 C124_U_TIDA-011008_ACDC_Leg1 C125_U_TIDA-011008_ACDC_Leg1 C126_U_TIDA-011008_ACDC_Leg1 C127_U_TIDA-011008_ACDC_Leg1 D13_U_TIDA-011008_ACDC_Leg1 D14_U_TIDA-011008_ACDC_Leg1 FB7_U_TIDA-011008_ACDC_Leg1 R171_U_TIDA-011008_ACDC_Leg1 R172_U_TIDA-011008_ACDC_Leg1 R173_U_TIDA-011008_ACDC_Leg1 R175_U_TIDA-011008_ACDC_Leg1 R176_U_TIDA-011008_ACDC_Leg1 R177_U_TIDA-011008_ACDC_Leg1 R178_U_TIDA-011008_ACDC_Leg1 R179_U_TIDA-011008_ACDC_Leg1 R180_U_TIDA-011008_ACDC_Leg1 R181_U_TIDA-011008_ACDC_Leg1 TP15_U_TIDA-011008_ACDC_Leg1 TP26_U_TIDA-011008_ACDC_Leg1 TP28_U_TIDA-011008_ACDC_Leg1 TP29_U_TIDA-011008_ACDC_Leg1 TP30_U_TIDA-011008_ACDC_Leg1 TP31_U_TIDA-011008_ACDC_Leg1 TP32_U_TIDA-011008_ACDC_Leg1 U15_U_TIDA-011008_ACDC_Leg1 U16_U_TIDA-011008_ACDC_Leg1 U17_U_TIDA-011008_ACDC_Leg1 U18_U_TIDA-011008_ACDC_Leg1 U21_U_TIDA-011008_ACDC_Leg1
component class "U_TIDA-011008_ACDC_EMI Filter": C24 C25 C26 C27 C28 C29 C30 C31 C32 C33 C34 C35 C36 C37 C38 C39 C40 C41 C134 C135 C136 C138 C139 C140 C141 D2 D3 F1 F2 FB2 FB3 FB4 FB9 J7 J8 J9 J10 K1 K2 K3 K4 L2 L3 Q1 Q2 R12 R13 R14 R15 R16 R17 R18 R19 R20 R21 R22 R23 R24 R25 R26 R27 R28 R29 R30 R31 R32 R33 R34 R35 R36 R37 R92 R93 R201 TP11 TP12 TP13 TP14 U3 U20 U23 U24
component class TIDA-011008_CoverSheet: C1 C2 C3 C4 C5 C6 C7 J1 J2 J3 J4
component class Header: J12 J13 J14 J15 J16 J17 J18 J19 J20 J21 J22

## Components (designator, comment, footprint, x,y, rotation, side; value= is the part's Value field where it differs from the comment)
C1 "ALH82D161DD600" FP-ALH82D161DD600_RADIAL-MFG 184.5,19.725 r0 top value=160µF
C2 "FCS2SDS505K050IC90B" FP-FCS2SDS505K050IC90B_RADIAL-MFG 151.049,69.8 r0 top value=5µF
C3 "ALH82D161DD600" FP-ALH82D161DD600_RADIAL-MFG 152.75,38.25 r0 top value=160µF
C4 "FCS2SDS505K050IC90B" FP-FCS2SDS505K050IC90B_RADIAL-MFG 151.125,84.5 r0 top value=5µF
C5 "ALH82D161DD600" FP-ALH82D161DD600_RADIAL-MFG 186.5,92.5 r0 top value=160µF
C6 "ALH82D161DD600" FP-ALH82D161DD600_RADIAL-MFG 186.5,55.5 r0 top value=160µF
C7 "CK45-B3FD222KYVNA" CK45_1250x600x1650 33,48.138 r180 top value=2200pF
C8 "R413F168050T0K" FP-R413F168050T0K_RADIAL-MFG 74,7.5 r90 top value=6.8nF
C9 "12103D226MAT2A" 1210_280 113.525,48.275 r0 top value=22uF
C10 "TMK316AB7106KLHT" 1206_180 118.315,47.525 r180 top value=10uF
C11 "GCM188R71H104KA57J" FP-GCM188R71H104KA57J_0603-MFG 120.2,46.991 r270 bottom value=100nF
C12 "FCS2SDS505K050IC90B" FP-FCS2SDS505K050IC90B_RADIAL-MFG 67.425,31.336 r270 top value=5µF
C13 "FCS2SDS505K050IC90B" FP-FCS2SDS505K050IC90B_RADIAL-MFG 82.494,31.336 r270 top value=5µF
C14 "C0603C221J5GAC7867" FP-C0603C221J5GAC7867_0603-MFG 115.185,43.35 r0 bottom value=220pF
C15 "C0603C221J5GAC7867" FP-C0603C221J5GAC7867_0603-MFG 112.775,45.475 r270 bottom value=220pF
C16 "FCS2SDS305K050I490B" FP-FCS2SDS305K050I490B_RADIAL-MFG 150.188,10.217 r180 top value=3µF
C17 "C1812V104KDRACTU" 1812_254 117.981,6.898 r270 bottom value=0.1uF
C18 "C1812V104KDRACTU" 1812_254 123.981,6.898 r270 bottom value=0.1uF
C19_U_TIDA-011008_ACDC_Leg1 "GRM188R71E474KA12D" 0603 173.033,119.922 r180 top value=0.47uF (schematic designator C19)
C19_U_TIDA-011008_ACDC_Leg2 "GRM188R71E474KA12D" 0603 119.367,107.862 r180 top value=0.47uF (schematic designator C19)
C20 "R413F168050T0K" FP-R413F168050T0K_RADIAL-MFG 63.5,7.5 r270 top value=6.8nF
C21 "TMK107BJ105KA-T" 0603 92.26,54.742 r90 bottom value=1uF
C22 "06033C104JAT2A" 0603 93.74,54.742 r90 bottom value=0.1uF
C23 "GRM1885C1H221JA01D" 0603 95.35,57.192 r90 bottom value=220pF
C24 "R413F168050T0K" FP-R413F168050T0K_RADIAL-MFG 151.25,183.5 r90 top value=6.8nF
C25 "DE6E3KJ222MN3A" E_900x700x900 195.665,189.5 r180 top value=2200pF
C26 "FCS3BAX475K050II90B" FP-FCS3BAX475K050II90B_RADIAL-MFG 172.25,193.25 r0 top value=4.7µF
C27 "FCS3BAX475K050II90B" FP-FCS3BAX475K050II90B_RADIAL-MFG 130.5,193 r0 top value=4.7µF
C28 "GCM188R71H104KA57J" FP-GCM188R71H104KA57J_0603-MFG 36.645,138.203 r180 top value=100nF
C29 "GCM188R71H104KA57J" FP-GCM188R71H104KA57J_0603-MFG 46.34,139.306 r180 top value=100nF
C30 "R413F168050T0K" FP-R413F168050T0K_RADIAL-MFG 151.25,197.5 r90 top value=6.8nF
C31 "DE6E3KJ222MN3A" E_900x700x900 195.915,165.75 r0 top value=2200pF
C32 "GRM188R71H221KA01D" 0603 22.698,95.973 r180 top value=220pF
C33 "GRM155R71C102KA01D" 0402 45.477,136.668 r90 top value=1000pF
C34 "GRM188R72A104KA35J" 0603 88.316,132.218 r180 top value=0.1uF
C35 "885012206089" 0603 85.139,143.144 r180 top value=0.01uF
C36 "TMK107BJ105KA-T" 0603 85.132,141.451 r180 top value=1uF
C37 "GRM188R71H221KA01D" 0603 10.024,103.203 r180 bottom value=220pF
C38 "GRM188R71H221KA01D" 0603 85.095,132.568 r0 top value=220pF
C39 "GRM188R71H221KA01D" 0603 85.147,139.98 r0 top value=220pF
C40 "GRM155R71C102KA01D" 0402 35.634,135.796 r90 top value=1000pF
C41 "GRM188R72A104KA35J" 0603 85.178,130.685 r180 top value=0.1uF
C42 "06033C104JAT2A" 0603 68.104,74.718 r90 top value=0.1uF
C43 "C0603X104K3RACTU" 0603 49.598,126.114 r270 top value=0.1uF
C44 "C0603C221K5RACTU" 0603 14.065,105.465 r0 bottom value=220pF
C45 "GRM188R71H221KA01D" 0603 51.098,129.256 r270 top value=220pF
C46 "GRM1885C1H162JA01D" 0603 67.224,72.218 r0 top value=1600pF
C47 "GRM1885C1H162JA01D" 0603 71.189,74.721 r270 top value=1600pF
C48 "C0603X104K3RACTU" 0603 53.793,131.043 r0 top value=0.1uF
C49 "06033C104JAT2A" 0603 64.001,125.125 r90 top value=0.1uF
C50 "GRM1885C1H561JA01D" 0603 62.154,121.726 r270 top value=560pF
C51 "GRM1885C1H561JA01D" 0603 62.154,126.58 r90 top value=560pF
C52 "GRM1885C1H561JA01D" 0603 50.267,123.717 r180 top value=560pF
C53 "GRM188R71H221KA01D" 0603 19.029,99.624 r270 bottom value=220pF
C54 "GRM188R71H221KA01D" 0603 13.774,109.965 r180 bottom value=220pF
C55 "GRM188R71H221KA01D" 0603 23.348,100.099 r270 bottom value=220pF
C56 "GRM1885C1H561JA01D" 0603 57.982,116.806 r180 top value=560pF
C57 "GRM1885C1H561JA01D" 0603 59.295,129.591 r180 top value=560pF
C58 "GRM1885C1H561JA01D" 0603 49.395,119.838 r90 top value=560pF
C59 "GRM1885C1H201JA01D" 0603 63.606,86.681 r0 top value=200pF
C60 "GRM1885C1H201JA01D" 0603 70.714,85.857 r270 top value=200pF
C61 "GRM188R71H221KA01D" 0603 13.835,97.999 r0 top value=220pF
C62 "GRM188R71H221KA01D" 0603 6.545,104.912 r90 top value=220pF
C63 "GRM1885C1H201JA01D" 0603 61.204,82.067 r90 top value=200pF
C64 "GRM1885C1H201JA01D" 0603 72.146,82.431 r90 top value=200pF
C65 "C1608X8R1E104K080AA" FP-C1608X8R1E104K080AA_0603-MFG 19.048,82.475 r180 bottom value=100nF
C66 "C1608X8R1E104K080AA" FP-C1608X8R1E104K080AA_0603-MFG 5.093,78.06 r90 bottom value=100nF
C67 "C1608X8R1E104K080AA" FP-C1608X8R1E104K080AA_0603-MFG 26.822,70.379 r90 bottom value=100nF
C68 "C1608X8R1E104K080AA" FP-C1608X8R1E104K080AA_0603-MFG 45.113,64.681 r270 bottom value=100nF
C69 "UWT1E101MCL1GS" UWT_630x770 101.501,69.812 r180 top value=100uF
C70 "GCE21BR71H104KA01L" FP-GCE21BR71H104KA01L_0805-MFG 88.533,81.484 r90 top
C71 "TMK107BJ105KA-T" 0603 82.808,72.658 r180 top value=1uF
C72 "TMK107BJ105KA-T" 0603 87.808,70.072 r90 top value=1uF
C73 "TMK107BJ105KA-T" 0603 44.477,61.408 r180 bottom value=1uF
C74 "TMK107BJ105KA-T" 0603 43.727,64.658 r270 bottom value=1uF
C75 "ZRB18AR61E106ME01L" FP-ZRB18AR61E106ME01L_0603-MFG 86.741,76.987 r0 top value=10µF
C76 "ZRB18AR61E106ME01L" FP-ZRB18AR61E106ME01L_0603-MFG 89,84.058 r0 top value=10µF
C77 "06033C104JAT2A" 0603 86.72,78.583 r180 top value=0.1uF
C78 "06033C104JAT2A" 0603 82.258,65.908 r180 top value=0.1uF
C79 "ZRB18AR61E106ME01L" FP-ZRB18AR61E106ME01L_0603-MFG 83.058,84.308 r180 top value=10µF
C80 "ZRB18AR61E106ME01L" FP-ZRB18AR61E106ME01L_0603-MFG 90.183,82.083 r90 top value=10µF
C81 "06033C104JAT2A" 0603 81.383,80.415 r90 top value=0.1uF
C82 "C0603C221K5RACTU" 0603 59.368,108.135 r90 top value=220pF
C83 "C0603C221K5RACTU" 0603 53.368,108.135 r90 top value=220pF
C84 "GCM188R71H104KA57J" FP-GCM188R71H104KA57J_0603-MFG 51.368,104.135 r90 top value=100nF
C85 "C0603C221K5RACTU" 0603 52.643,97.135 r270 top value=220pF
C86 "C0603C221K5RACTU" 0603 59.682,97.135 r270 top value=220pF
C87 "C0603C221K5RACTU" 0603 64.406,97.135 r270 top value=220pF
C88 "C0603C221K5RACTU" 0603 65.368,108.135 r90 top value=220pF
C89 "GCM188R71H104KA57J" FP-GCM188R71H104KA57J_0603-MFG 70.432,103.606 r90 top value=100nF
C90 "C0603C221K5RACTU" 0603 71.182,96.206 r180 top value=220pF
C91 "C0603C221K5RACTU" 0603 75.669,96.681 r270 top value=220pF
C92 "GCM155L81E104KE02D" 0402 22.84,112.777 r90 bottom value=0.1uF
C93 "GCM155L81E104KE02D" 0402 19.504,111.277 r90 bottom value=0.1uF
C94 "GCM155L81E104KE02D" 0402 26.415,111.577 r0 bottom value=0.1uF
C95 "GRM188Z71A106KA73D" FP-GRM188Z71A106KA73D_0603-MFG 26.413,112.879 r0 bottom value=10µF
C96 "C0603C221K5RACTU" 0603 71.319,108.155 r90 top value=220pF
C97 "CC0603KRX7R7BB225" 0603 20.74,109.056 r180 bottom value=2.2uF
C98 "CC0603KRX7R7BB225" 0603 19.965,106.677 r90 bottom value=2.2uF
C99 "GCM155L81E104KE02D" 0402 26.415,110.552 r180 bottom value=0.1uF
C100 "GCM155L81E104KE02D" 0402 21.665,112.777 r270 bottom value=0.1uF
C101 "C0603C221K5RACTU" 0603 77.519,108.181 r90 top value=220pF
C102 "C0603C221K5RACTU" 0603 13.59,114.365 r180 top value=220pF
C103 "CC0603KRX7R7BB225" 0603 23.895,108.415 r90 bottom value=2.2uF
C104 "CC0603KRX7R7BB225" 0603 26.19,109.19 r180 bottom value=2.2uF
C105 "GRM188C61E226ME01J" FP-GRM188C61E226ME01J_0603-MFG 216.5,5 r0 top value=22µF
C106 "C1608X8R1E104K080AA" FP-C1608X8R1E104K080AA_0603-MFG 216.5,6.207 r0 top value=100nF
C107 "C1608X8R1E104K080AA" FP-C1608X8R1E104K080AA_0603-MFG 249.69,12.66 r270 top value=100nF
C108_U_TIDA-011008_ACDC_Leg1 "GCM188R71H104KA57J" FP-GCM188R71H104KA57J_0603-MFG 167.337,107.229 r0 top value=100nF (schematic designator C108)
C108_U_TIDA-011008_ACDC_Leg2 "GCM188R71H104KA57J" FP-GCM188R71H104KA57J_0603-MFG 113.242,95.233 r0 top value=100nF (schematic designator C108)
C109_U_TIDA-011008_ACDC_Leg1 "GCM188R71H104KA57J" FP-GCM188R71H104KA57J_0603-MFG 167.912,117.275 r270 bottom value=100nF (schematic designator C109)
C109_U_TIDA-011008_ACDC_Leg2 "GCM188R71H104KA57J" FP-GCM188R71H104KA57J_0603-MFG 113.917,105.183 r270 bottom value=100nF (schematic designator C109)
C110_U_TIDA-011008_ACDC_Leg1 "12103D226MAT2A" 1210_280 168.75,122.25 r0 top value=22uF (schematic designator C110)
C110_U_TIDA-011008_ACDC_Leg2 "12103D226MAT2A" 1210_280 114.5,110.071 r0 top value=22uF (schematic designator C110)
C111_U_TIDA-011008_ACDC_Leg1 "TMK316AB7106KLHT" 1206_180 168.789,119.5 r0 top value=10uF (schematic designator C111)
C111_U_TIDA-011008_ACDC_Leg2 "TMK316AB7106KLHT" 1206_180 114.493,107.449 r0 top value=10uF (schematic designator C111)
C112_U_TIDA-011008_ACDC_Leg1 "TMK316AB7106KLHT" 1206_180 173.05,124.719 r0 bottom value=10uF (schematic designator C112)
C112_U_TIDA-011008_ACDC_Leg2 "TMK316AB7106KLHT" 1206_180 118.793,112.827 r0 bottom value=10uF (schematic designator C112)
C113_U_TIDA-011008_ACDC_Leg1 "GCM188R71H104KA57J" FP-GCM188R71H104KA57J_0603-MFG 172.069,128.517 r180 top value=100nF (schematic designator C113)
C113_U_TIDA-011008_ACDC_Leg2 "GCM188R71H104KA57J" FP-GCM188R71H104KA57J_0603-MFG 117.855,116.65 r180 top value=100nF (schematic designator C113)
C114_U_TIDA-011008_ACDC_Leg1 "C0603C221J5GAC7867" FP-C0603C221J5GAC7867_0603-MFG 172.544,116.992 r180 bottom value=220pF (schematic designator C114)
C114_U_TIDA-011008_ACDC_Leg2 "C0603C221J5GAC7867" FP-C0603C221J5GAC7867_0603-MFG 118.804,104.668 r180 bottom value=220pF (schematic designator C114)
C115_U_TIDA-011008_ACDC_Leg1 "C0603C221J5GAC7867" FP-C0603C221J5GAC7867_0603-MFG 172.121,127.136 r180 top value=220pF (schematic designator C115)
C115_U_TIDA-011008_ACDC_Leg2 "C0603C221J5GAC7867" FP-C0603C221J5GAC7867_0603-MFG 118.042,115.158 r180 top value=220pF (schematic designator C115)
C116_U_TIDA-011008_ACDC_Leg1 "C0603C221J5GAC7867" FP-C0603C221J5GAC7867_0603-MFG 171.03,106.507 r270 top value=220pF (schematic designator C116)
C116_U_TIDA-011008_ACDC_Leg2 "C0603C221J5GAC7867" FP-C0603C221J5GAC7867_0603-MFG 116.742,94.308 r270 top value=220pF (schematic designator C116)
C117_U_TIDA-011008_ACDC_Leg1 "GCM188R71H104KA57J" FP-GCM188R71H104KA57J_0603-MFG 173.221,125.125 r0 top value=100nF (schematic designator C117)
C117_U_TIDA-011008_ACDC_Leg2 "GCM188R71H104KA57J" FP-GCM188R71H104KA57J_0603-MFG 119.367,112.633 r0 top value=100nF (schematic designator C117)
C118_U_TIDA-011008_ACDC_Leg1 "06033C104JAT2A" 0603 162.699,114.795 r180 bottom value=0.1uF (schematic designator C118)
C118_U_TIDA-011008_ACDC_Leg2 "06033C104JAT2A" 0603 108.855,102.299 r180 bottom value=0.1uF (schematic designator C118)
C119_U_TIDA-011008_ACDC_Leg1 "C1812V104KDRACTU" 1812_254 188.33,136.604 r0 bottom value=0.1uF (schematic designator C119)
C119_U_TIDA-011008_ACDC_Leg2 "C1812V104KDRACTU" 1812_254 134.235,124.608 r0 bottom value=0.1uF (schematic designator C119)
C120_U_TIDA-011008_ACDC_Leg1 "0603ZC102KAT2A" 0603 10.024,105.749 r180 bottom value=1000pF (schematic designator C120)
C120_U_TIDA-011008_ACDC_Leg2 "0603ZC102KAT2A" 0603 23.599,91.421 r0 bottom value=1000pF (schematic designator C120)
C121_U_TIDA-011008_ACDC_Leg1 "C1812V104KDRACTU" 1812_254 188.33,125.965 r0 bottom value=0.1uF (schematic designator C121)
C121_U_TIDA-011008_ACDC_Leg2 "C1812V104KDRACTU" 1812_254 134.235,114.566 r0 bottom value=0.1uF (schematic designator C121)
C122_U_TIDA-011008_ACDC_Leg1 "C1812V104KDRACTU" 1812_254 188.33,131.354 r0 bottom value=0.1uF (schematic designator C122)
C122_U_TIDA-011008_ACDC_Leg2 "C1812V104KDRACTU" 1812_254 134.235,119.697 r0 bottom value=0.1uF (schematic designator C122)
C123_U_TIDA-011008_ACDC_Leg1 "12103D226MAT2A" 1210_280 147.066,122.198 r180 top value=22uF (schematic designator C123)
C123_U_TIDA-011008_ACDC_Leg2 "12103D226MAT2A" 1210_280 92.347,109.14 r180 top value=22uF (schematic designator C123)
C124_U_TIDA-011008_ACDC_Leg1 "TMK316AB7106KLHT" 1206_180 146.974,123.623 r180 bottom value=10uF (schematic designator C124)
C124_U_TIDA-011008_ACDC_Leg2 "TMK316AB7106KLHT" 1206_180 92.292,111.505 r180 bottom value=10uF (schematic designator C124)
C125_U_TIDA-011008_ACDC_Leg1 "GCM188R71H104KA57J" FP-GCM188R71H104KA57J_0603-MFG 146.038,129.279 r0 bottom value=100nF (schematic designator C125)
C125_U_TIDA-011008_ACDC_Leg2 "GCM188R71H104KA57J" FP-GCM188R71H104KA57J_0603-MFG 92.053,117.486 r0 bottom value=100nF (schematic designator C125)
C126_U_TIDA-011008_ACDC_Leg1 "C0603C221J5GAC7867" FP-C0603C221J5GAC7867_0603-MFG 148.478,125.527 r180 bottom value=220pF (schematic designator C126)
C126_U_TIDA-011008_ACDC_Leg2 "C0603C221J5GAC7867" FP-C0603C221J5GAC7867_0603-MFG 94.5,113.539 r180 bottom value=220pF (schematic designator C126)
C127_U_TIDA-011008_ACDC_Leg1 "C0603C221J5GAC7867" FP-C0603C221J5GAC7867_0603-MFG 152.244,128.95 r180 top value=220pF (schematic designator C127)
C127_U_TIDA-011008_ACDC_Leg2 "C0603C221J5GAC7867" FP-C0603C221J5GAC7867_0603-MFG 98.54,117.053 r180 top value=220pF (schematic designator C127)
C128 "CC0603KRX7R7BB225" 0603 16.665,104.067 r90 bottom value=2.2uF
C129 "C0603C221K5RACTU" 0603 49.868,100.885 r270 top value=220pF
C130 "06033C104JAT2A" 0603 18.747,135.95 r90 top value=0.1uF
C131 "GRM1885C1H561JA01D" 0603 25.865,141.307 r0 top value=560pF
C132 "GRM188R71H221KA01D" 0603 29.145,92.637 r90 top value=220pF
C133 "GRM1885C1H561JA01D" 0603 22.435,134.448 r180 top value=560pF
C134 "GRM188R71H221KA01D" 0603 38.648,157.654 r90 bottom value=220pF
C135 "ZRB18AR61E106ME01L" FP-ZRB18AR61E106ME01L_0603-MFG 38.942,181.11 r0 bottom value=10µF
C136 "06033C104JAT2A" 0603 38.892,182.715 r180 bottom value=0.1uF
C137 "GRM188R71C104KA01D" 0603 59.221,86.976 r180 top value=0.1uF
C138 "ZRB18AR61E106ME01L" FP-ZRB18AR61E106ME01L_0603-MFG 39.649,135.086 r180 top value=10µF
C139 "ZRB18AR61E106ME01L" FP-ZRB18AR61E106ME01L_0603-MFG 49.87,136.048 r180 top value=10µF
C140 "GRM188R71H221KA01D" 0603 10.244,98.983 r0 bottom value=220pF
C141 "GRM188R71H221KA01D" 0603 20.938,99.98 r270 bottom value=220pF
D1 "WNSC6D20650B6J" FP-WNSC6D20650B6J_TO263-MFG 113.956,17.878 r180 top
D2 "B160-13-F" SMA 43.694,142.193 r90 top value=60V
D3 "B160-13-F" SMA 33.5,141.025 r90 top value=60V
D6 "KG DELLS1.22-JGKH-24" "FP-KG DELLS1.22-JGKH-24_0603-MFG" 93.933,62.545 r270 top
D7 "KG DELLS1.22-JGKH-24" "FP-KG DELLS1.22-JGKH-24_0603-MFG" 92.033,62.545 r270 top
D8 "KG DELLS1.22-JGKH-24" "FP-KG DELLS1.22-JGKH-24_0603-MFG" 90.012,62.545 r270 top
D10 "GBLC03-LF-T7" SOD-323 80.288,96.642 r90 top value=3.3V
D11 "GBLC03-LF-T7" SOD-323 74.452,108.194 r90 top value=3.3V
D12 "GBLC03-LF-T7" SOD-323 82.112,108.181 r270 top value=3.3V
D13_U_TIDA-011008_ACDC_Leg1 "WNSC6D02650P6X" FP-WNSC6D02650P6X_SOD123-IPC_C 159.742,121.384 r180 top (schematic designator D13)
D13_U_TIDA-011008_ACDC_Leg2 "WNSC6D02650P6X" FP-WNSC6D02650P6X_SOD123-IPC_C 105.647,109.388 r180 top (schematic designator D13)
D14_U_TIDA-011008_ACDC_Leg1 "BZT52C16-7-F" SOD-123 168.937,122.404 r0 bottom value=16V (schematic designator D14)
D14_U_TIDA-011008_ACDC_Leg2 "BZT52C16-7-F" SOD-123 114.598,110.254 r0 bottom value=16V (schematic designator D14)
D15 "WNSC6D20650B6J" FP-WNSC6D20650B6J_TO263-MFG 127.088,17.878 r180 top
F1 "SF-3812F2000T-2" FP-SF-3812F2000T-2_3812-MFG 21.25,178.775 r90 top
F2 "SF-3812F2000T-2" FP-SF-3812F2000T-2_3812-MFG 21.25,162.147 r270 top
FB1 "MH1608-601Y" FP-MH1608-601Y_0603-MFG 90.125,56.215 r0 bottom
FB2 "MH1608-601Y" FP-MH1608-601Y_0603-MFG 20.406,96.787 r90 top
FB3 "MH1608-601Y" FP-MH1608-601Y_0603-MFG 9.84,101.757 r0 bottom
FB4 "MH1608-601Y" FP-MH1608-601Y_0603-MFG 88.57,130.855 r0 top
FB5 "MH1608-601Y" FP-MH1608-601Y_0603-MFG 66.579,75.177 r270 top
FB6 "MH1608-601Y" FP-MH1608-601Y_0603-MFG 61.427,124.332 r180 top
FB7_U_TIDA-011008_ACDC_Leg1 "MH1608-601Y" FP-MH1608-601Y_0603-MFG 165.104,114.736 r90 bottom (schematic designator FB7)
FB7_U_TIDA-011008_ACDC_Leg2 "MH1608-601Y" FP-MH1608-601Y_0603-MFG 111.26,102.24 r90 bottom (schematic designator FB7)
FB8 "MH1608-601Y" FP-MH1608-601Y_0603-MFG 20.132,135.623 r90 top
FB9 "MH1608-601Y" FP-MH1608-601Y_0603-MFG 38.923,179.756 r0 bottom
FID1 "Fiducial" Fiducial10-20 75.25,200.625 r90 top
FID2 "Fiducial" Fiducial10-20 10.25,6.505 r90 top
FID3 "Fiducial" Fiducial10-20 201.786,140.64 r90 top
J1 "74650073R" Wurth_WP-THRBU 8.315,179.1 r0 top
J2 "74650073R" Wurth_WP-THRBU 11.25,195 r0 top
J3 "1714955" Phoenix_1714955 13.75,29.75 r270 top
J4 "74650073R" Wurth_WP-THRBU 8.315,161.573 r0 top
J5 "74650073R" Wurth_WP-THRBU 85.85,5.725 r90 top
J6 "74650073R" Wurth_WP-THRBU 102.435,30.5 r90 top
J7 "74650073R" Wurth_WP-THRBU 176.25,151.5 r0 top
J8 "74650073R" Wurth_WP-THRBU 176.25,173.75 r0 top
J9 "74650073R" Wurth_WP-THRBU 118.032,134.353 r0 top
J10 "74650073R" Wurth_WP-THRBU 158.312,160 r0 top
J11 "694106402002" FP-694106402002_CONN_PWR_10MM7_9MM0-MFG 97.649,87.915 r0 top
J12 "TSW-110-08-G-S" Samtec_TSW-110-08-x-S 115.917,69.942 r270 top
J13 "PBC04SAAN" Sullins_xxC04SAAN 5.92,84.879 r0 top
J14 "PBC04SAAN" Sullins_xxC04SAAN 6.082,60.39 r270 top
J15 "PBC04SAAN" Sullins_xxC04SAAN 44.202,71.91 r90 top
J16 "61300611121" WURTH_61300611121 40.399,105.667 r90 top
J17 "PBC03DAAN" Sullins_PBC03DAAN 240.335,19.55 r180 top
J18 "PBC04SAAN" Sullins_xxC04SAAN 249.44,21.495 r90 top
J19 "PBC04SAAN" Sullins_xxC04SAAN 211.32,9.955 r270 top
J20 "PRPC016SAAN-RC" Sullins_xxxC016SAAN 230.97,2.225 r0 top
J21 "PRPC016SAAN-RC" Sullins_xxxC016SAAN 230.97,29.975 r0 top
J22 "PBC04SAAN" Sullins_xxC04SAAN 5.92,92.516 r0 top
J23 "U.FL-R-SMT-1(01)" CONN_UFL-R-SMT-1 211.07,19.725 r180 top
K1 "G5PZ-1A-E DC12" "FP-G5PZ-1A-E DC12_PTH_RELAY_23MM8_10MM3-MFG" 95.132,164.191 r270 top
K2 "G5PZ-1A-E DC12" "FP-G5PZ-1A-E DC12_PTH_RELAY_23MM8_10MM3-MFG" 83.68,164.191 r270 top
K3 "G5PZ-1A-E DC12" "FP-G5PZ-1A-E DC12_PTH_RELAY_23MM8_10MM3-MFG" 92.75,198 r0 top
K4 "G5PZ-1A-E DC12" "FP-G5PZ-1A-E DC12_PTH_RELAY_23MM8_10MM3-MFG" 92.75,186.5 r0 top
L1 "YXA80182T-3" FP-YXA80182T-3_pth4-MFG 43,28.5 r270 top
L2 "YXA80182T-3" FP-YXA80182T-3_pth4-MFG 62,169.5 r180 top
L3 "YXA80182T-3" FP-YXA80182T-3_pth4-MFG 130.5,165.5 r90 top
L5 "SRN3015-100M" SRN3015 90.183,78.608 r0 top value=10uH
L6 "742792602" 0603 1.961,81.631 r90 bottom value="60 ohm"
L7 "742792602" 0603 21.465,106.702 r270 bottom value="60 ohm"
L8 "742792602" 0603 26.19,107.69 r0 bottom value="60 ohm"
LBL1 "THT-14-423-10" Label_650x200 5.675,143.038 r90 top
Logo1 "Texas Instruments" TI_Stacked_Overlay_Small 33.244,88.25 r0 top
Logo2 "CE Mark" CE_Mark_5mm 14.5,53.938 r0 top
Logo3 "FCC disclaimer" FCC_disclaimer 35.953,46.096 r0 top
Logo4 "WEEE logo" WEEE_Minimum 21.75,55.857 r0 top
LOGO5 "CAUTION HOT SURFACE" IEC_HotSurface_Medium 42.4,56.37 r0 top
LOGO6 "DANGER HIGH VOLTAGE" IEC_HighVoltage_Medium 30.593,56.136 r0 top
MP1 "9774030960R" FP-9774030960R_SPACER-MFG#1 5.489,44.645 r180 bottom
MP2 "9774030960R" FP-9774030960R_SPACER-MFG#2 98.448,16.86 r180 bottom
MP3 "9774030960R" FP-9774030960R_SPACER-MFG#2 199.665,152.295 r180 bottom
MP4 "9774030960R" FP-9774030960R_SPACER-MFG#2 129.01,143.85 r180 bottom
MP5 "9774030960R" FP-9774030960R_SPACER-MFG#2 59.25,196.25 r180 bottom
MP6 "9774030960R" FP-9774030960R_SPACER-MFG#2 151.561,105.608 r180 bottom
MP7 "9774030960R" FP-9774030960R_SPACER-MFG#2 199.951,114.529 r180 bottom
MP8 "9774030960R" FP-9774030960R_SPACER-MFG#2 199.75,200 r180 bottom
MP9 "9774030960R" FP-9774030960R_SPACER-MFG#2 78.75,121.176 r180 bottom
MP10 "9774030960R" FP-9774030960R_SPACER-MFG#2 200.243,73.899 r180 bottom
MP11 "9774030960R" FP-9774030960R_SPACER-MFG#2 200.125,5 r180 bottom
MP12 "9774030960R" FP-9774030960R_SPACER-MFG#2 134.391,54.654 r180 bottom
Q1 "CSD17585F5T" YJK0003A 46.898,143.989 r180 top value=30V
Q2 "CSD17585F5T" YJK0003A 36.614,143.095 r180 top value=30V
R1 "CRCW06031R00JNEA" 0603 118.79,49 r0 bottom value=1.0
R2 "B72314S2461K101" FP-B72314S2461K101_RADIAL-MFG 34,7.85 r180 top
R3 "RC0603FR-0751RL" 0603 115.75,45.441 r270 bottom value=51.0
R4 "B72314S2461K101" FP-B72314S2461K101_RADIAL-MFG 21.4,11.75 r270 top
R5 "RC0603FR-0743K2L" 0603 114.25,45.475 r270 bottom value=43.2k
R6 "B72314S2461K101" FP-B72314S2461K101_RADIAL-MFG 49.5,7.85 r0 top
R7 "CSS2H-2512K-2L00F" FP-CSS2H-2512K-2L00F_2512-MFG 93.265,47.79 r0 bottom value=2m
R8 "CRCW060356R0JNEA" 0603 95.35,53.867 r90 bottom value=56
R9 "CRCW060310K0FKEAC" FP-CRCW060310K0FKEAC_0603-MFG 90.575,53.609 r90 bottom value=10k
R10 "CRCW06031K00FKEAC" FP-CRCW06031K00FKEAC_0603-MFG 90.575,51.359 r90 bottom value=1k
R11 "CRCW060356R0JNEA" 0603 89.125,53.867 r90 bottom value=56
R12 "PTCEL13R600LBE" FP-PTCEL13R600LBE_RADIAL-MFG 109.75,182 r90 top value=60Ω
R13 "IsoM5-275-B-L2" FP-IsoM5-275-B-L2_RADIAL-MFG 25.338,196 r90 top
R14 "ERJ-8ENF1693V" 1206 200.165,182.45 r90 top value=169k
R15 "ERJ-8ENF1693V" 1206 197.665,182.45 r90 top value=169k
R16 "ERJ-8ENF1693V" 1206 195.165,182.45 r90 top value=169k
R17 "IsoM5-275-B-L2" FP-IsoM5-275-B-L2_RADIAL-MFG 34,195.952 r270 top
R18 "ERJ-8ENF1693V" 1206 200.165,177.5 r90 top value=169k
R19 "ERJ-8ENF1693V" 1206 197.665,177.5 r90 top value=169k
R20 "ERJ-8ENF1693V" 1206 195.165,177.5 r90 top value=169k
R21 "ERJ-8ENF1693V" 1206 200.165,172.6 r90 top value=169k
R22 "ERJ-8ENF1693V" 1206 197.665,172.6 r90 top value=169k
R23 "ERJ-8ENF1693V" 1206 195.165,172.6 r90 top value=169k
R24 "IsoM5-275-B-L2" FP-IsoM5-275-B-L2_RADIAL-MFG 42.75,195.952 r270 top
R25 "PTCEL13R600LBE" FP-PTCEL13R600LBE_RADIAL-MFG 109.75,197 r270 top value=60Ω
R26 "CRCW060356R0JNEA" 0603 88.321,136.89 r180 top value=56
R27 "ESR03EZPJ101" 0603 47.302,141.601 r90 top value=100
R28 "RC1608J103CS" 0603 46.898,136.626 r270 top value=10k
R29 "RC0603JR-0710KL" 0603 88.277,141.446 r180 top value=10k
R30 "RC0603JR-0710KL" 0603 88.321,133.959 r180 top value=10k
R31 "CRCW060356R0JNEA" 0603 88.327,138.39 r0 top value=56
R32 "CRCW060356R0JNEA" 0603 88.321,135.415 r180 top value=56
R33 "CRCW060356R0JNEA" 0603 88.295,139.98 r180 top value=56
R34 "ESR03EZPJ101" 0603 37.607,140.904 r90 top value=100
R35 "CRCW060310K0FKEAC" FP-CRCW060310K0FKEAC_0603-MFG 88.57,129.585 r180 top value=10k
R36 "RC1608J103CS" 0603 36.951,135.754 r270 top value=10k
R37 "CRCW06031K00FKEAC" FP-CRCW06031K00FKEAC_0603-MFG 86.26,129.327 r0 top value=1k
R38 "RG1608P-103-B-T5" 0603 51.098,126.114 r90 top value=10.0k
R39 "CRCW0603100RFKEAHP" 0603 63.319,75.652 r0 top value=100
R40 "CRCW0603100RFKEAHP" 0603 72.064,78.668 r90 top value=100
R41 "RC0603FR-0756RL" 0603 61.204,78.343 r90 top value=56.0
R42 "RC0603FR-0756RL" 0603 73.654,78.668 r90 top value=56.0
R43 "RC1206FR-07680KL" 1206 62.574,55.432 r90 top value=680k
R44 "RC1206FR-07680KL" 1206 62.574,60.189 r90 top value=680k
R45 "RC1206FR-07680KL" 1206 62.619,64.782 r90 top value=680k
R46 "RC1206FR-07560KL" 1206 73.256,55.762 r90 top value=560k
R47 "RC1206FR-07560KL" 1206 73.256,60.512 r90 top value=560k
R48 "RC1206FR-07560KL" 1206 73.256,65.232 r90 top value=560k
R49 "CRCW060356R0JNEA" 0603 53.793,129.397 r0 top value=56
R50 "RG1608P-103-B-T5" 0603 49.598,129.251 r90 top value=10.0k
R51 "RCG060310K0FKEA" 0603 67.224,70.718 r180 top value=10.0k
R52 "RCG060310K0FKEA" 0603 69.761,74.721 r90 top value=10.0k
R53 "RC0603FR-0710RL" 0603 69.761,71.418 r90 top value=10.0
R54 "RC0603FR-0756RL" 0603 67.224,69.193 r180 top value=56.0
R55 "RCG060310K0FKEA" 0603 60.476,121.74 r270 top value=10.0k
R56 "RCG060310K0FKEA" 0603 60.476,126.58 r90 top value=10.0k
R57 "RCG060310K0FKEA" 0603 50.267,122.192 r180 top value=10.0k
R58 "RC1206FR-071ML" 1206 63.221,146.75 r270 top value=1.00Meg
R59 "RC1206FR-071ML" 1206 63.221,142.042 r270 top value=1.00Meg
R60 "RC1206FR-071ML" 1206 63.221,137.202 r270 top value=1.00Meg
R61 "RC1206FR-071ML" 1206 59.34,146.803 r270 top value=1.00Meg
R62 "RC1206FR-071ML" 1206 59.34,142.094 r270 top value=1.00Meg
R63 "RC1206FR-071ML" 1206 59.34,137.254 r270 top value=1.00Meg
R64 "RC1206FR-071ML" 1206 77.153,144.322 r270 top value=1.00Meg
R65 "RC1206FR-071ML" 1206 76.706,139.542 r270 top value=1.00Meg
R66 "RC1206FR-071ML" 1206 76.706,134.702 r270 top value=1.00Meg
R67 "RC0603FR-0780R6L" 0603 60.376,117.539 r270 top value=80.6
R68 "RC0603FR-0780R6L" 0603 59.295,132.827 r180 top value=80.6
R69 "RC0603FR-0780R6L" 0603 53.068,118.263 r0 top value=80.6
R70 "RC1206FR-071ML" 1206 68.201,144.271 r270 top value=1.00Meg
R71 "RC1206FR-071ML" 1206 68.201,139.562 r270 top value=1.00Meg
R72 "RC1206FR-071ML" 1206 68.201,134.723 r270 top value=1.00Meg
R73 "RC1206FR-071ML" 1206 54.595,146.877 r270 top value=1.00Meg
R74 "RC1206FR-071ML" 1206 54.995,142.1 r270 top value=1.00Meg
R75 "RC1206FR-071ML" 1206 54.995,137.26 r270 top value=1.00Meg
R76 "RC1206FR-071ML" 1206 72.136,144.243 r270 top value=1.00Meg
R77 "RC1206FR-071ML" 1206 72.136,139.535 r270 top value=1.00Meg
R78 "RC1206FR-071ML" 1206 72.136,134.695 r270 top value=1.00Meg
R79 "RCG060310K0FKEA" 0603 57.982,118.339 r180 top value=10.0k
R80 "RCG060310K0FKEA" 0603 59.295,131.237 r180 top value=10.0k
R81 "RCG060310K0FKEA" 0603 50.842,119.838 r90 top value=10.0k
R82 "CRCW06037K32FKEA" 0603 63.606,85.05 r180 top value=7.32k
R83 "CRCW06037K32FKEA" 0603 69.22,85.857 r90 top value=7.32k
R84 "CRCW06037K32FKEA" 0603 65.904,85.84 r90 top value=7.32k
R85 "CRCW06037K32FKEA" 0603 67.589,85.857 r90 top value=7.32k
R86 "CRCW060356R0JNEA" 0603 60.479,84.483 r180 top value=56
R87 "CRCW060356R0JNEA" 0603 72.318,85.84 r90 top value=56
R88 "CRCW06037K32FKEA" 0603 58.222,82.063 r90 top value=7.32k
R89 "CRCW06037K32FKEA" 0603 75.154,82.431 r90 top value=7.32k
R90 "CRCW06037K32FKEA" 0603 59.678,82.061 r270 top value=7.32k
R91 "CRCW06037K32FKEA" 0603 73.574,82.431 r270 top value=7.32k
R92 "RC1608J103CS" 0603 48.964,143.31 r270 top value=10k
R93 "RC1608J103CS" 0603 39.3,142.572 r270 top value=10k
R98 "RC0603JR-075K6L" 0603 93.933,65.495 r90 top value=5.6k
R99 "ERJ-3GEYJ152V" 0603 92.033,65.495 r270 top value=1.5k
R100 "RC0603JR-07680RL" 0603 90.012,65.495 r270 top value=680
R101 "RCG060310K0FKEA" 0603 81.259,70.072 r90 top value=10.0k
R102 "RCG060310K0FKEA" 0603 84.358,80.417 r270 top value=10.0k
R103 "RC0603FR-07105KL" 0603 85.925,84.132 r0 top value=105k
R104 "CRCW06032K70JNEA" 0603 82.258,67.408 r180 top value=2.7k
R105 "ERJ-3EKF2002V" 0603 82.733,82.808 r0 top value=20.0k
R106 "CRCW06032K10FKEA" 0603 82.808,80.419 r90 top value=2.10k
R107 "CR0603-JW-472GLF" 0603 51.368,100.885 r90 top value=4.7k
R108 "CRCW06038R20JNEA" 0603 54.189,97.135 r90 top value=8.2
R109 "CRCW060382R0JNEA" 0603 56.733,97.135 r90 top value=82
R110 "RCS06030000Z0EA" 0603 28.563,119.077 r90 top value=0
R111 "CRCW06038R20JNEA" 0603 61.268,97.135 r90 top value=8.2
R112 "RCS06030000Z0EA" 0603 30.063,119.077 r90 top value=0
R113 "CRCW060382R0JNEA" 0603 62.393,108.135 r270 top value=82
R114 "RCS06030000Z0EA" 0603 31.563,119.077 r90 top value=0
R115 "CRCW060382R0JNEA" 0603 58.003,108.135 r270 top value=82
R116 "CRCW060382R0JNEA" 0603 60.793,108.135 r90 top value=82
R117 "RCS06030000Z0EA" 0603 33.063,119.077 r90 top value=0
R118 "CRCW060382R0JNEA" 0603 54.963,108.135 r270 top value=82
R119 "CRCW060382R0JNEA" 0603 56.618,108.135 r90 top value=82
R120 "RCS06030000Z0EA" 0603 32.846,115.475 r0 top value=0
R121 "RCS06030000Z0EA" 0603 21.04,119.077 r90 top value=0
R122 "RCS06030000Z0EA" 0603 16.54,119.077 r90 top value=0
R123 "RCS06030000Z0EA" 0603 22.54,119.077 r90 top value=0
R124 "RCS06030000Z0EA" 0603 32.846,114.1 r0 top value=0
R125 "RCS06030000Z0EA" 0603 19.54,119.077 r90 top value=0
R126 "RCS06030000Z0EA" 0603 18.015,119.077 r90 top value=0
R127 "RCS06030000Z0EA" 0603 24.04,119.077 r90 top value=0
